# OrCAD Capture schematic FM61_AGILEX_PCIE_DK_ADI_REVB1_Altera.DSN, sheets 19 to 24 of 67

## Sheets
19 FPGA BANK 2C: size B
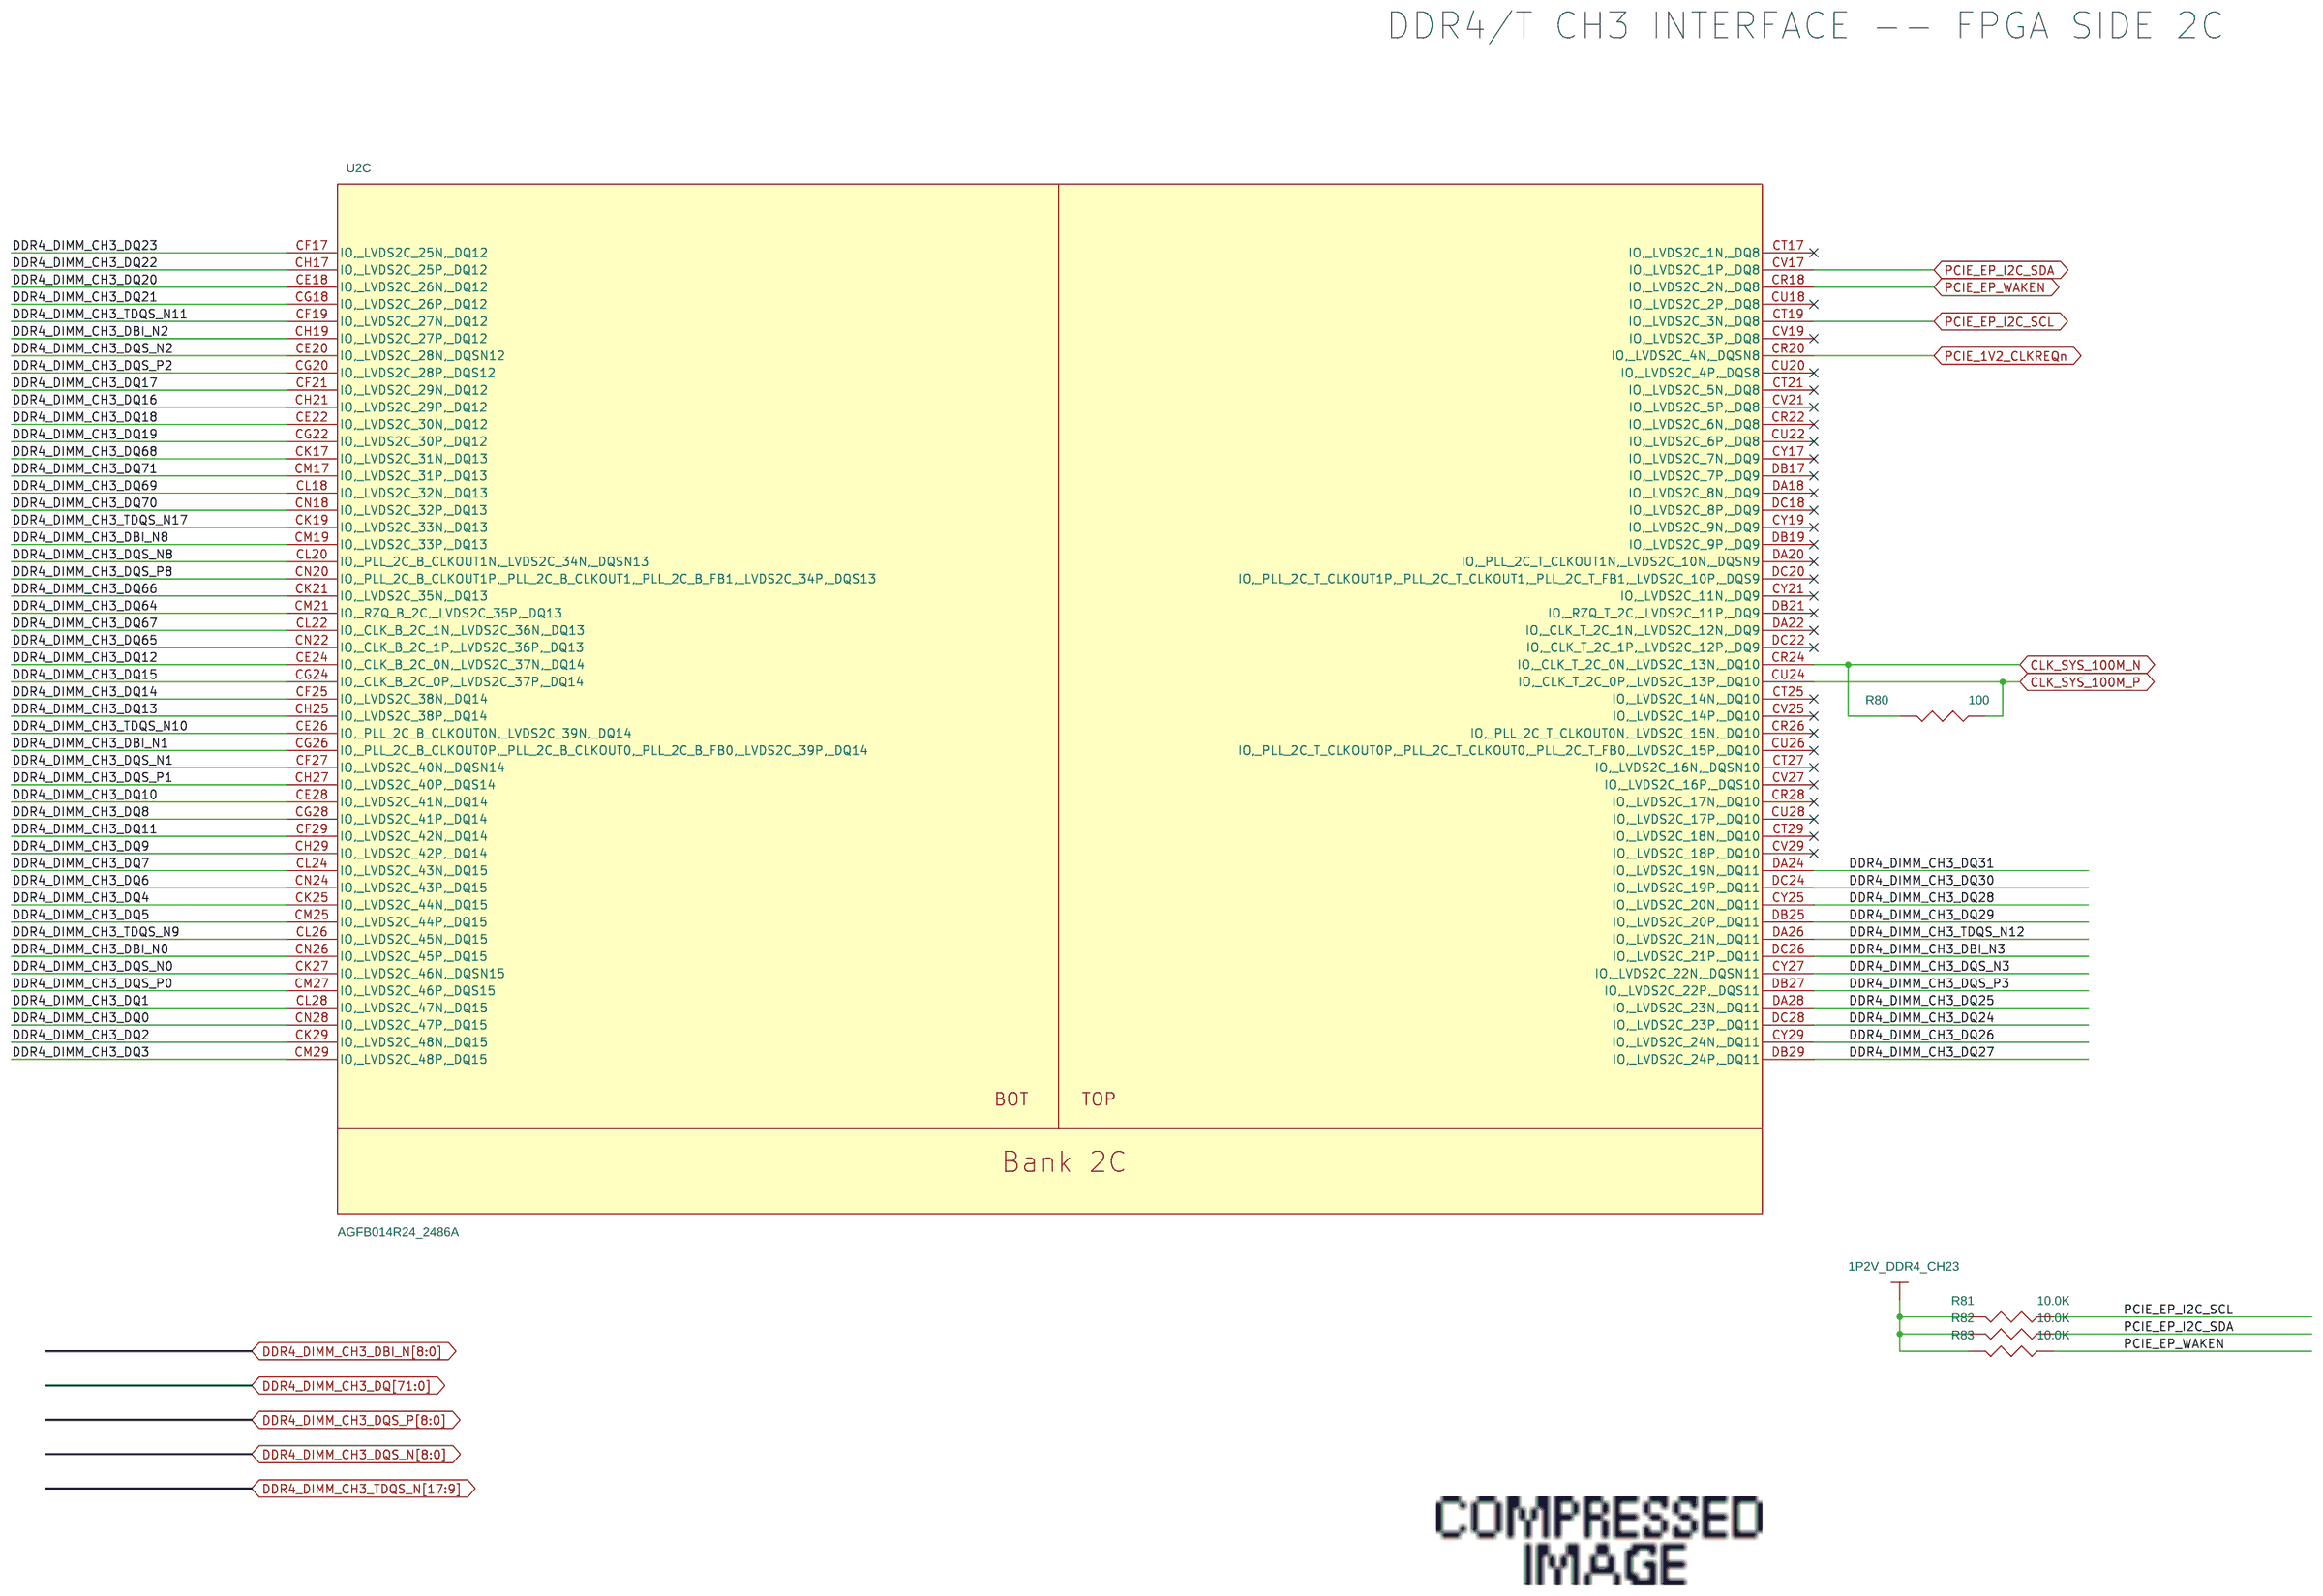
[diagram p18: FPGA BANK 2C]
20 FPGA BANK 2D: size B
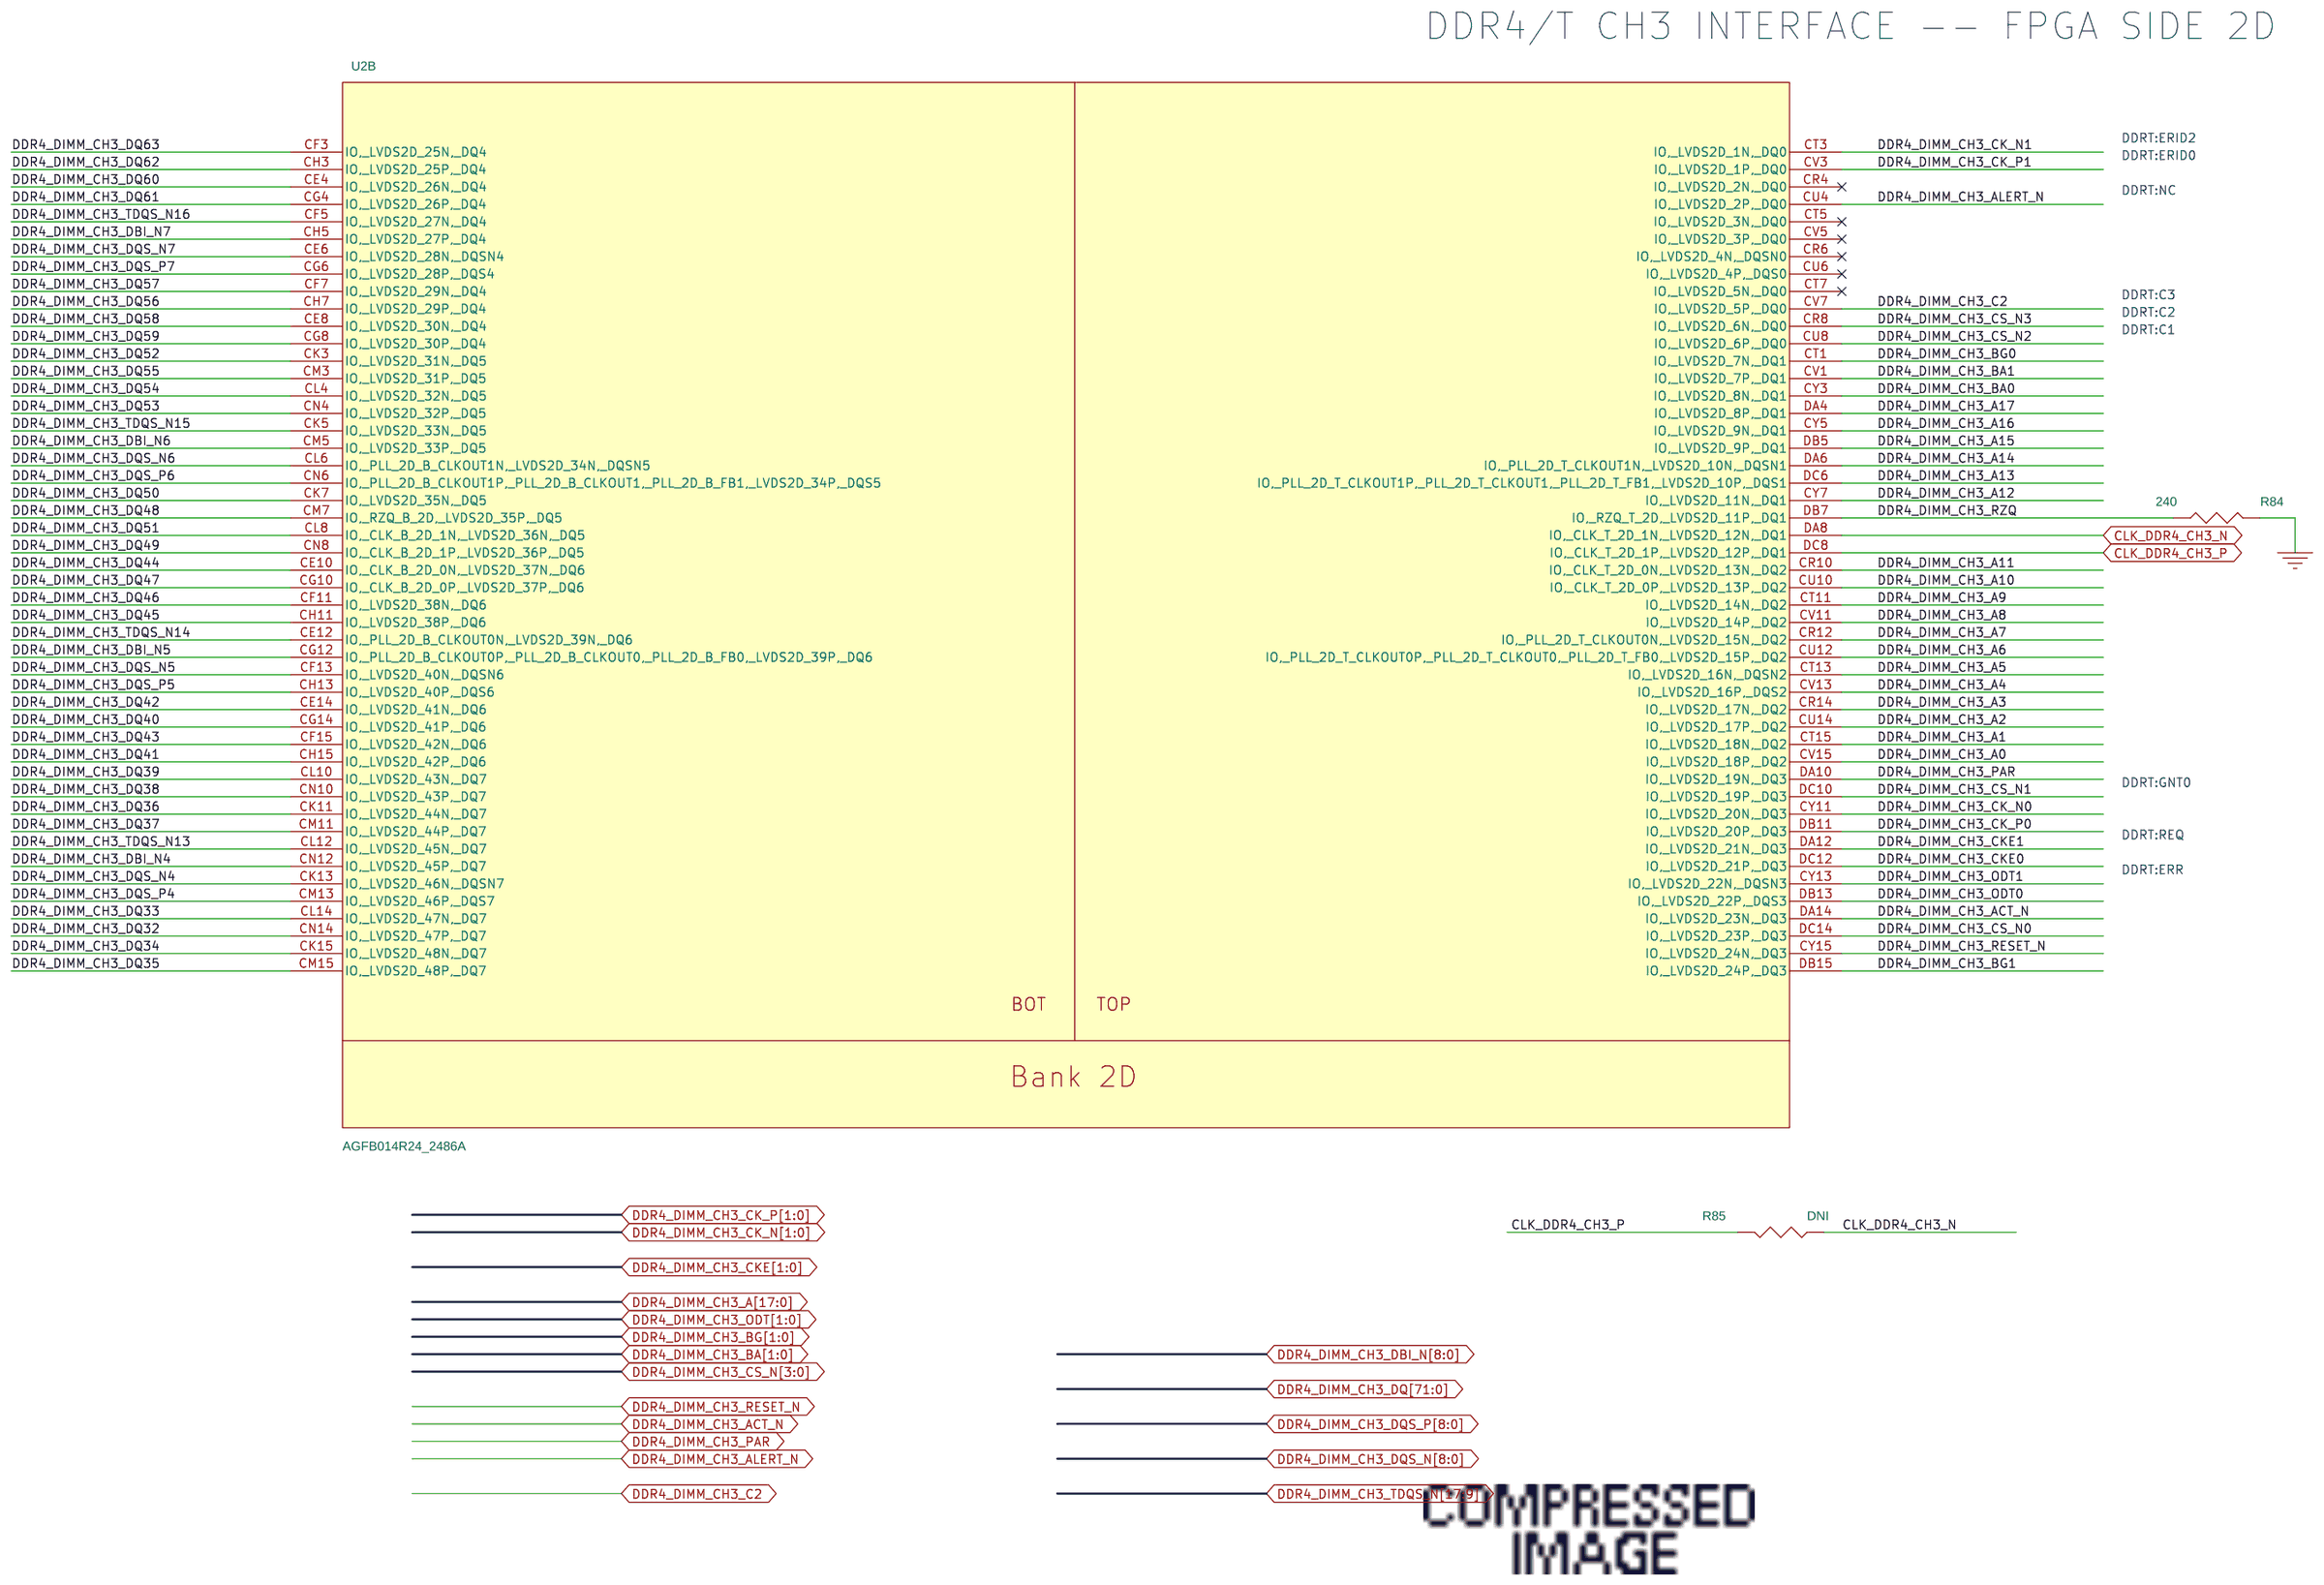
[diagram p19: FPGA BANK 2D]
21 FPGA BANK 9A: size B
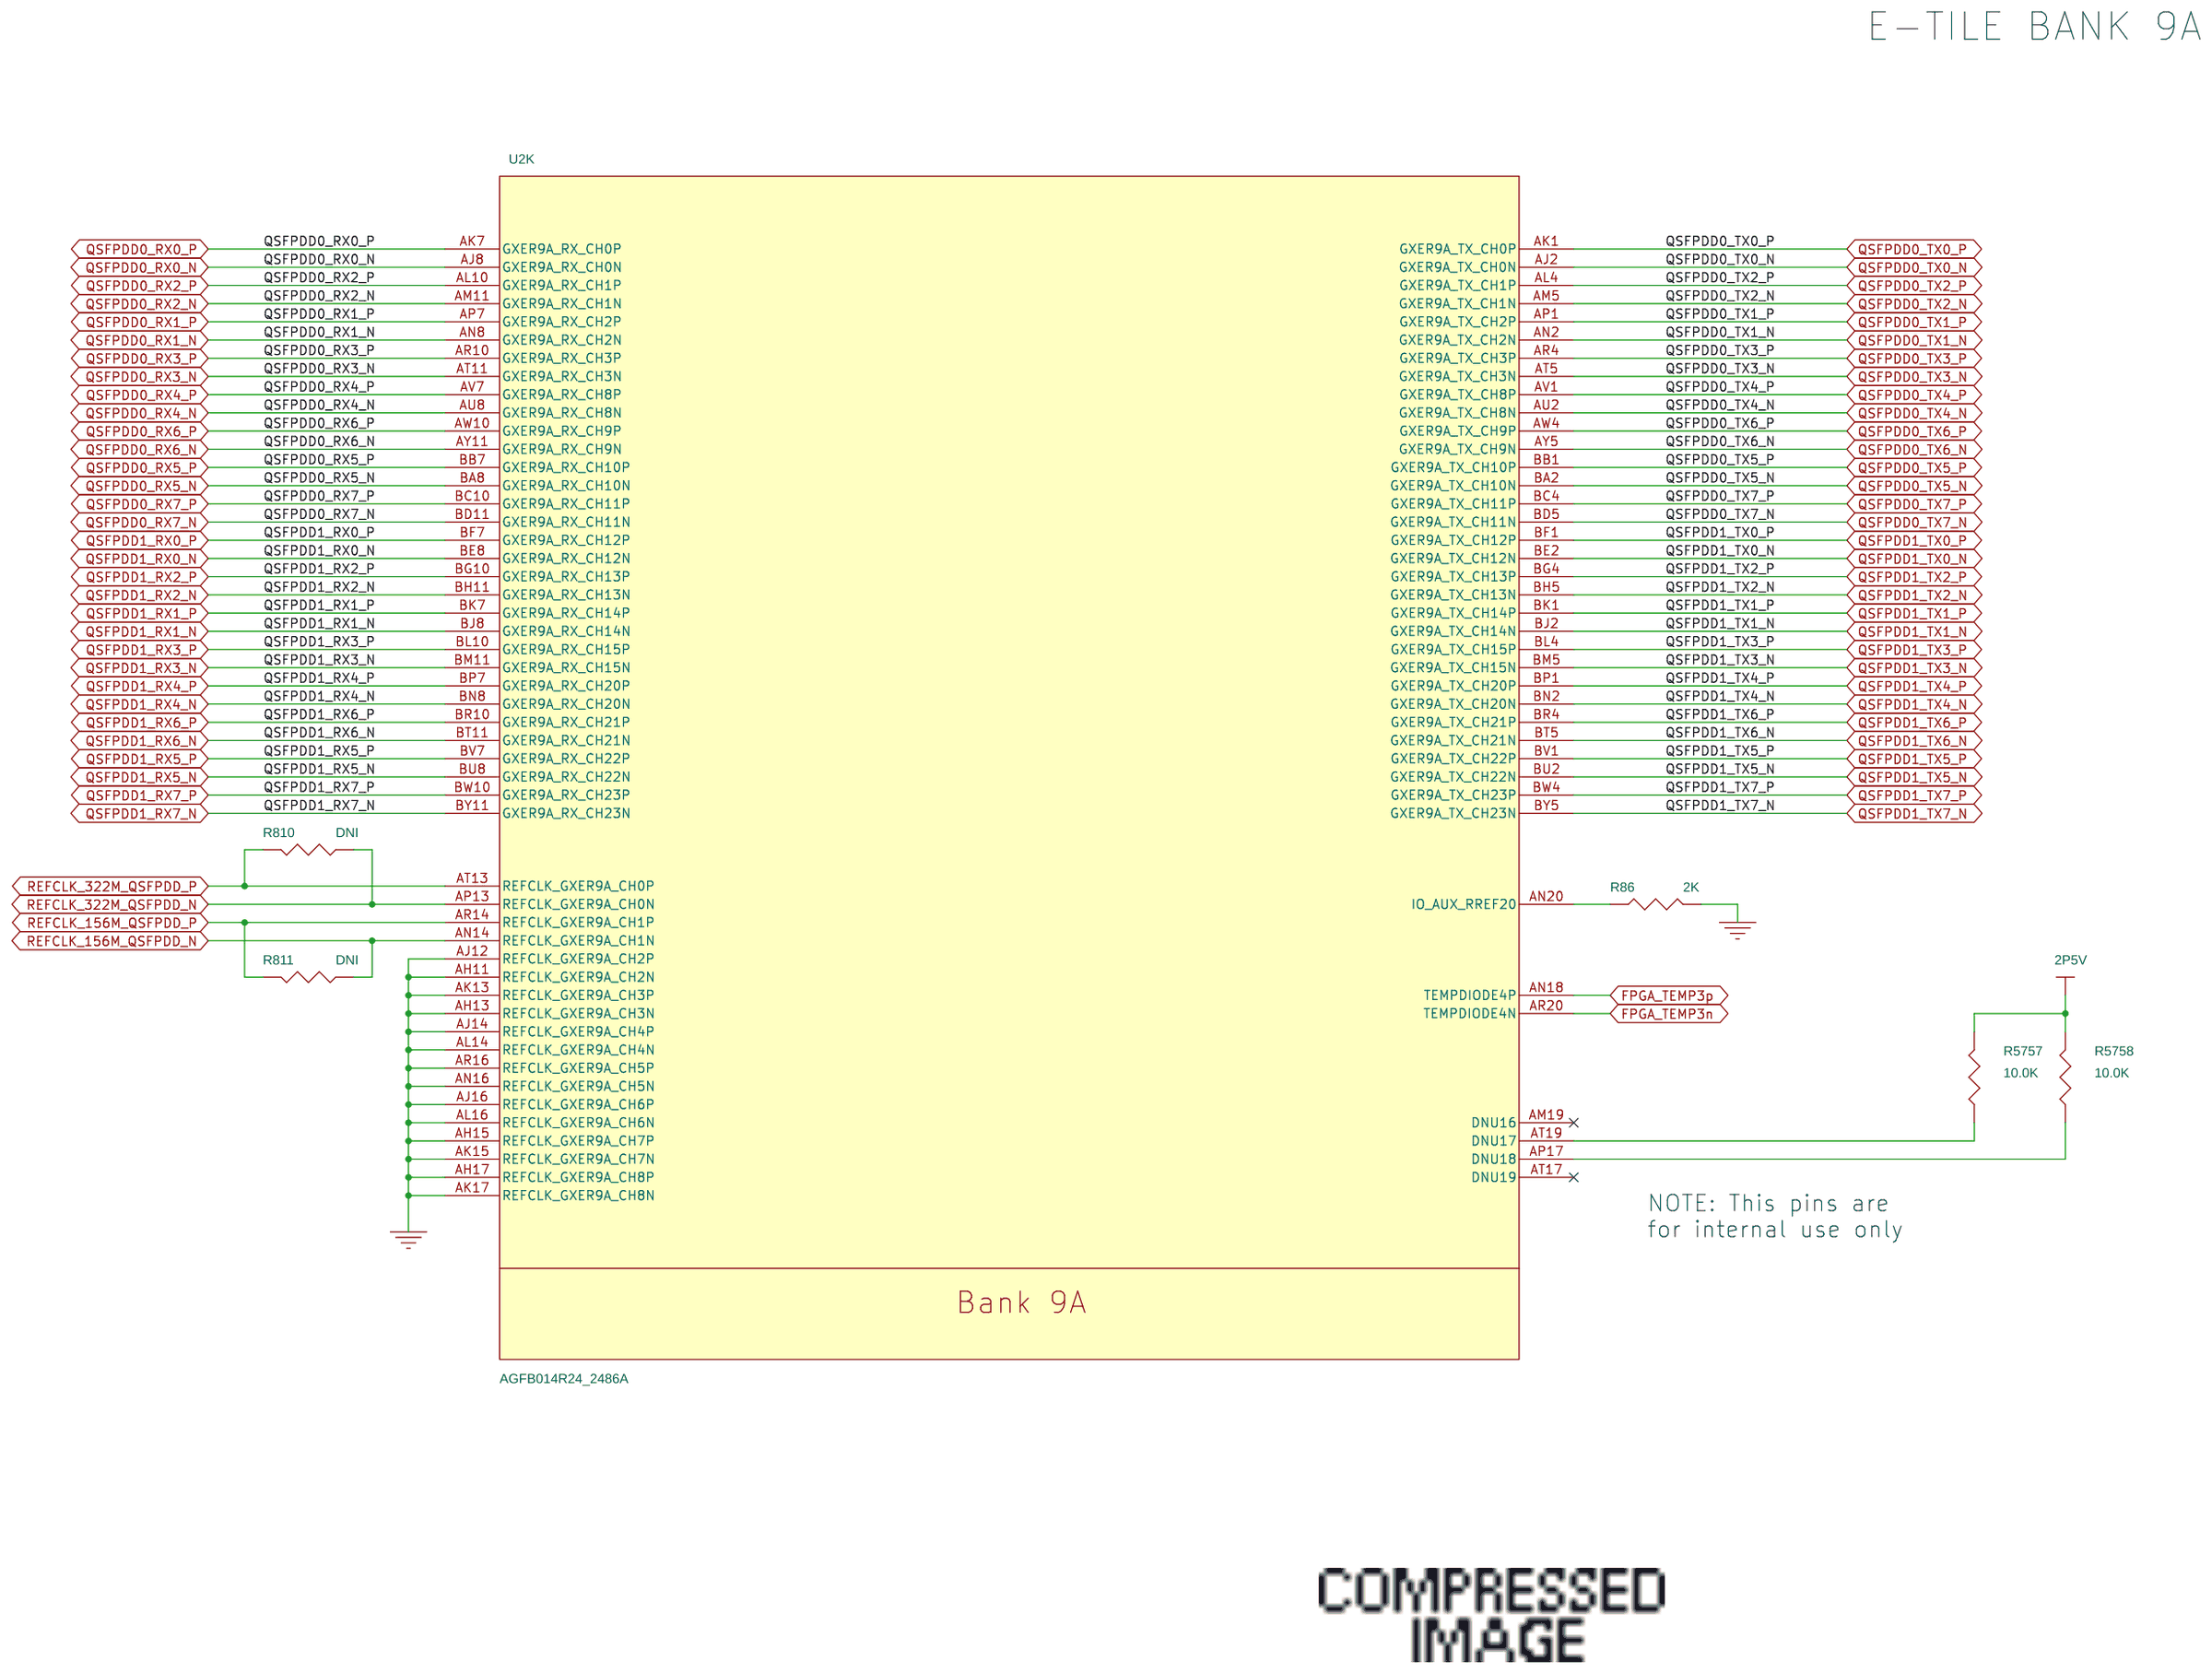
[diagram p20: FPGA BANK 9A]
22 FPGA BANK 10A: size B
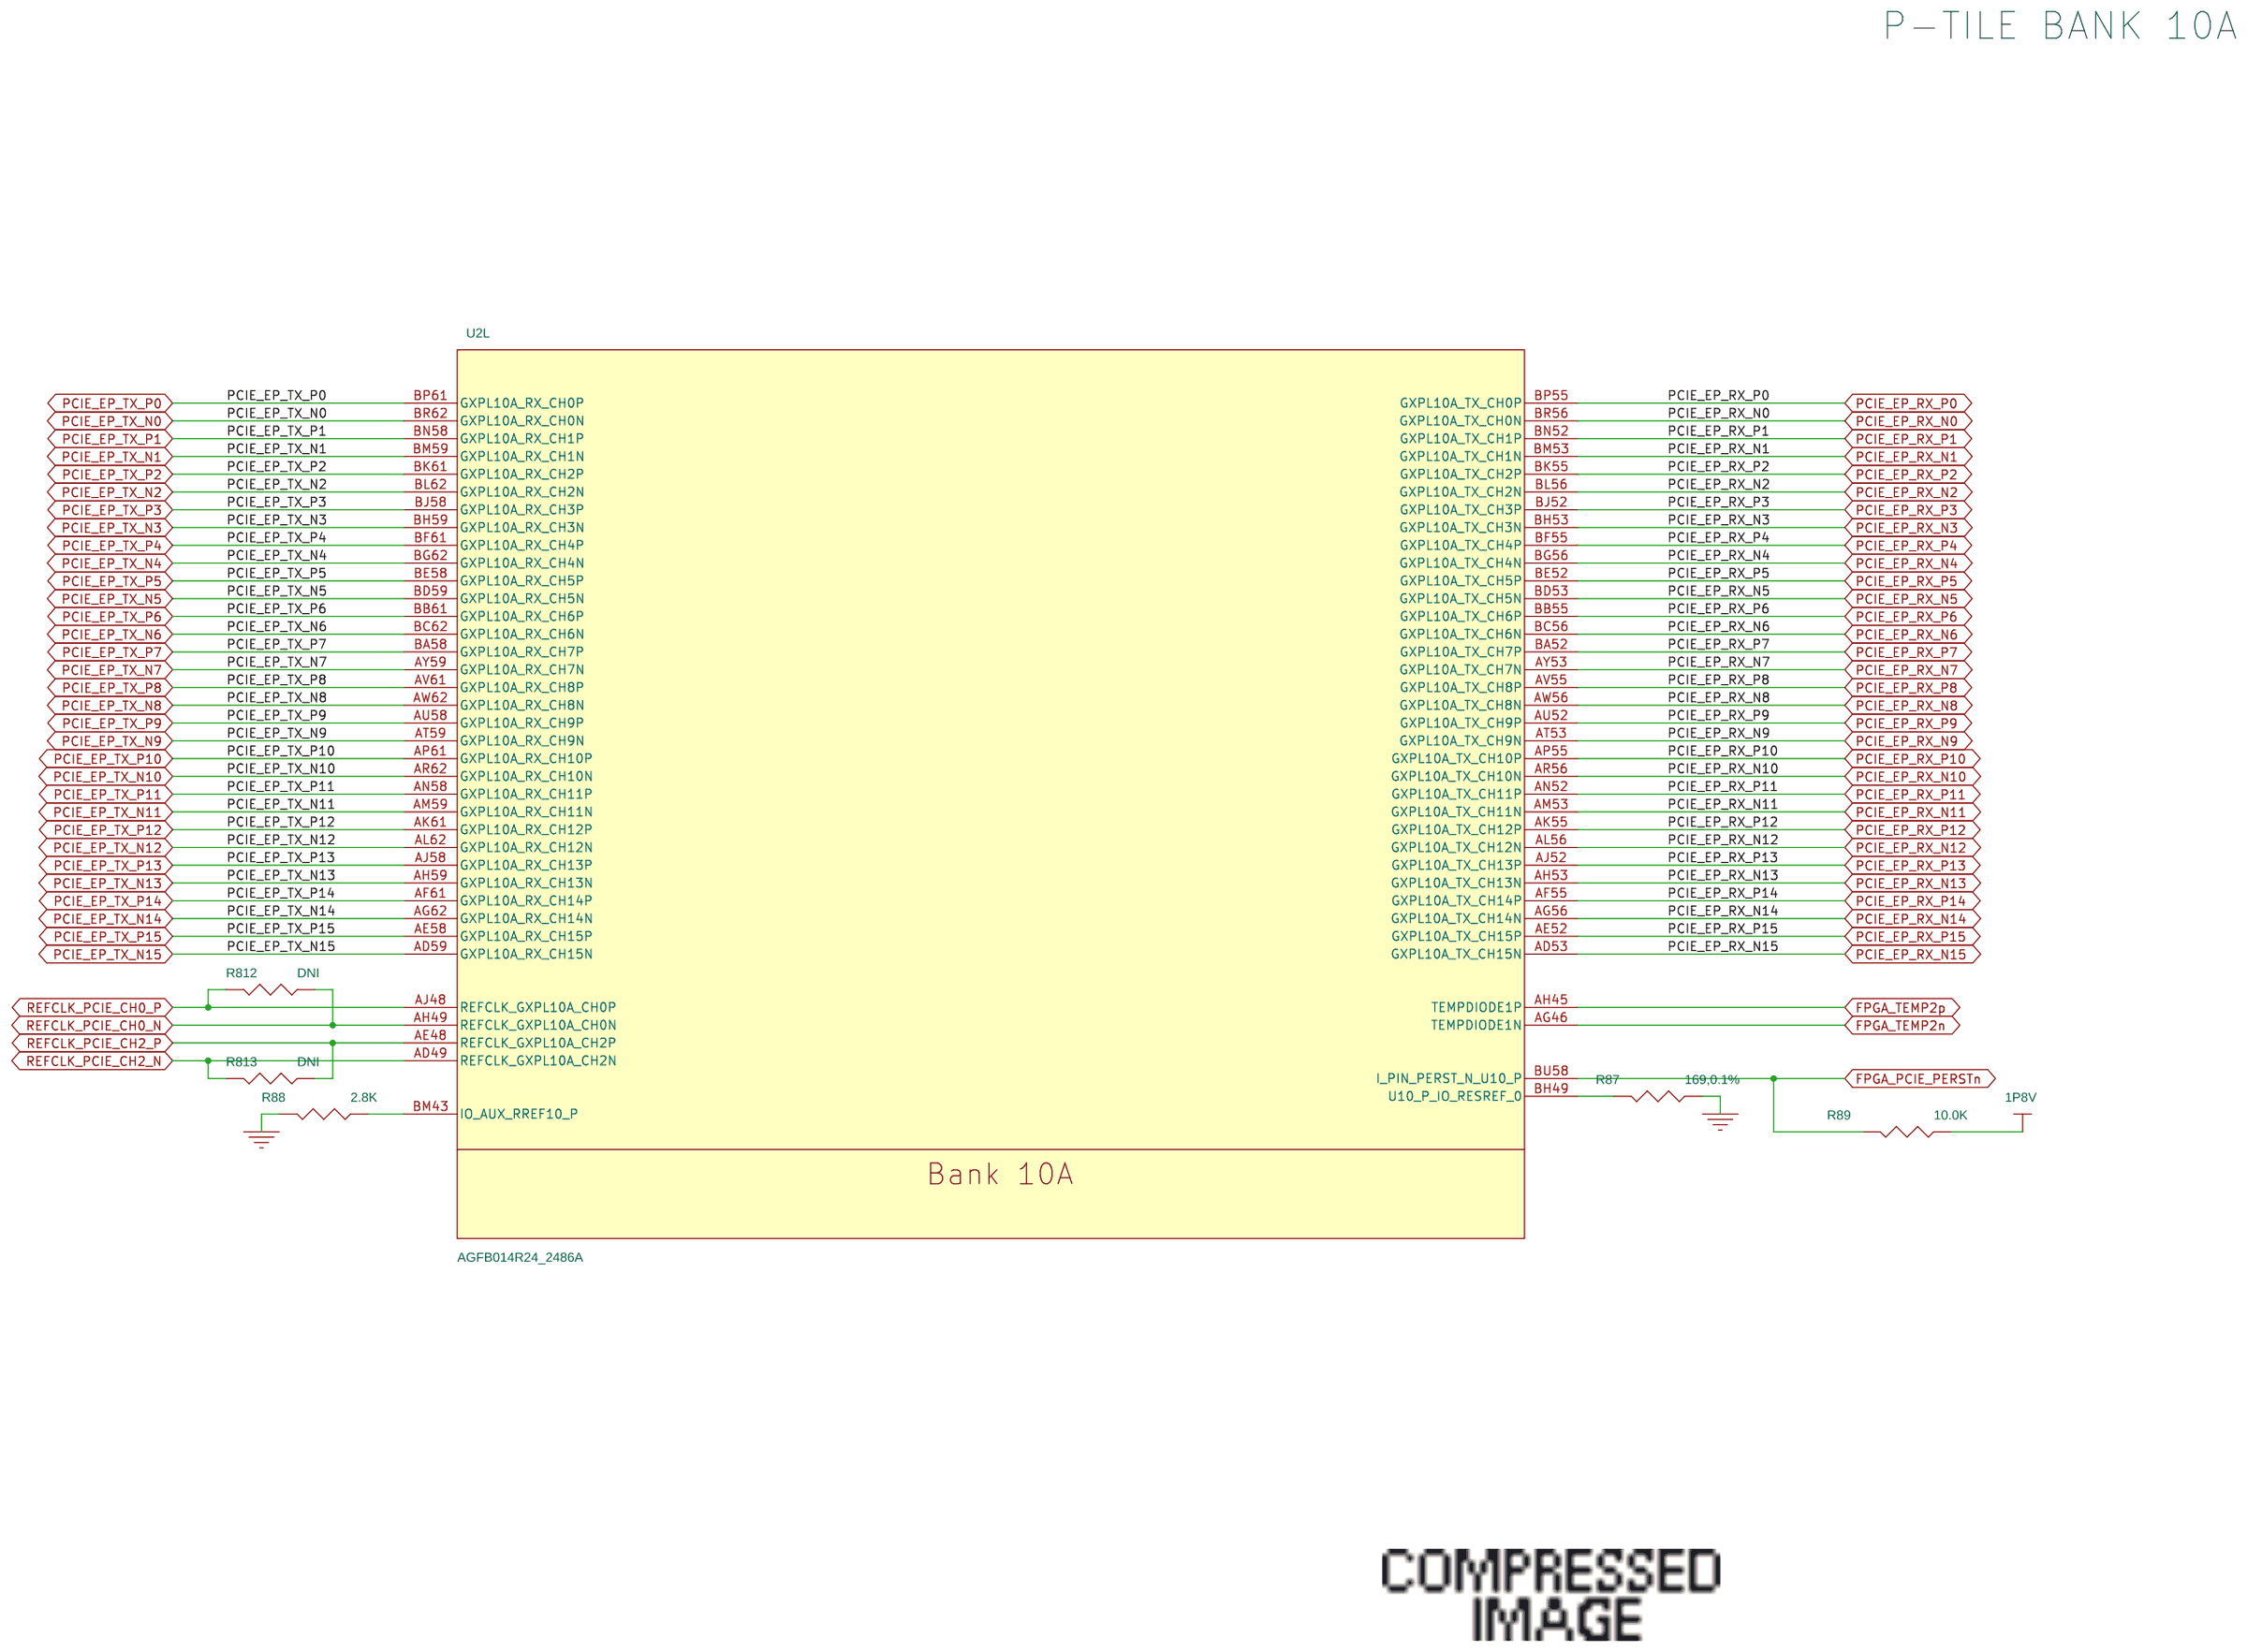
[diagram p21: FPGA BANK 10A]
23 QSFPDD0: size B
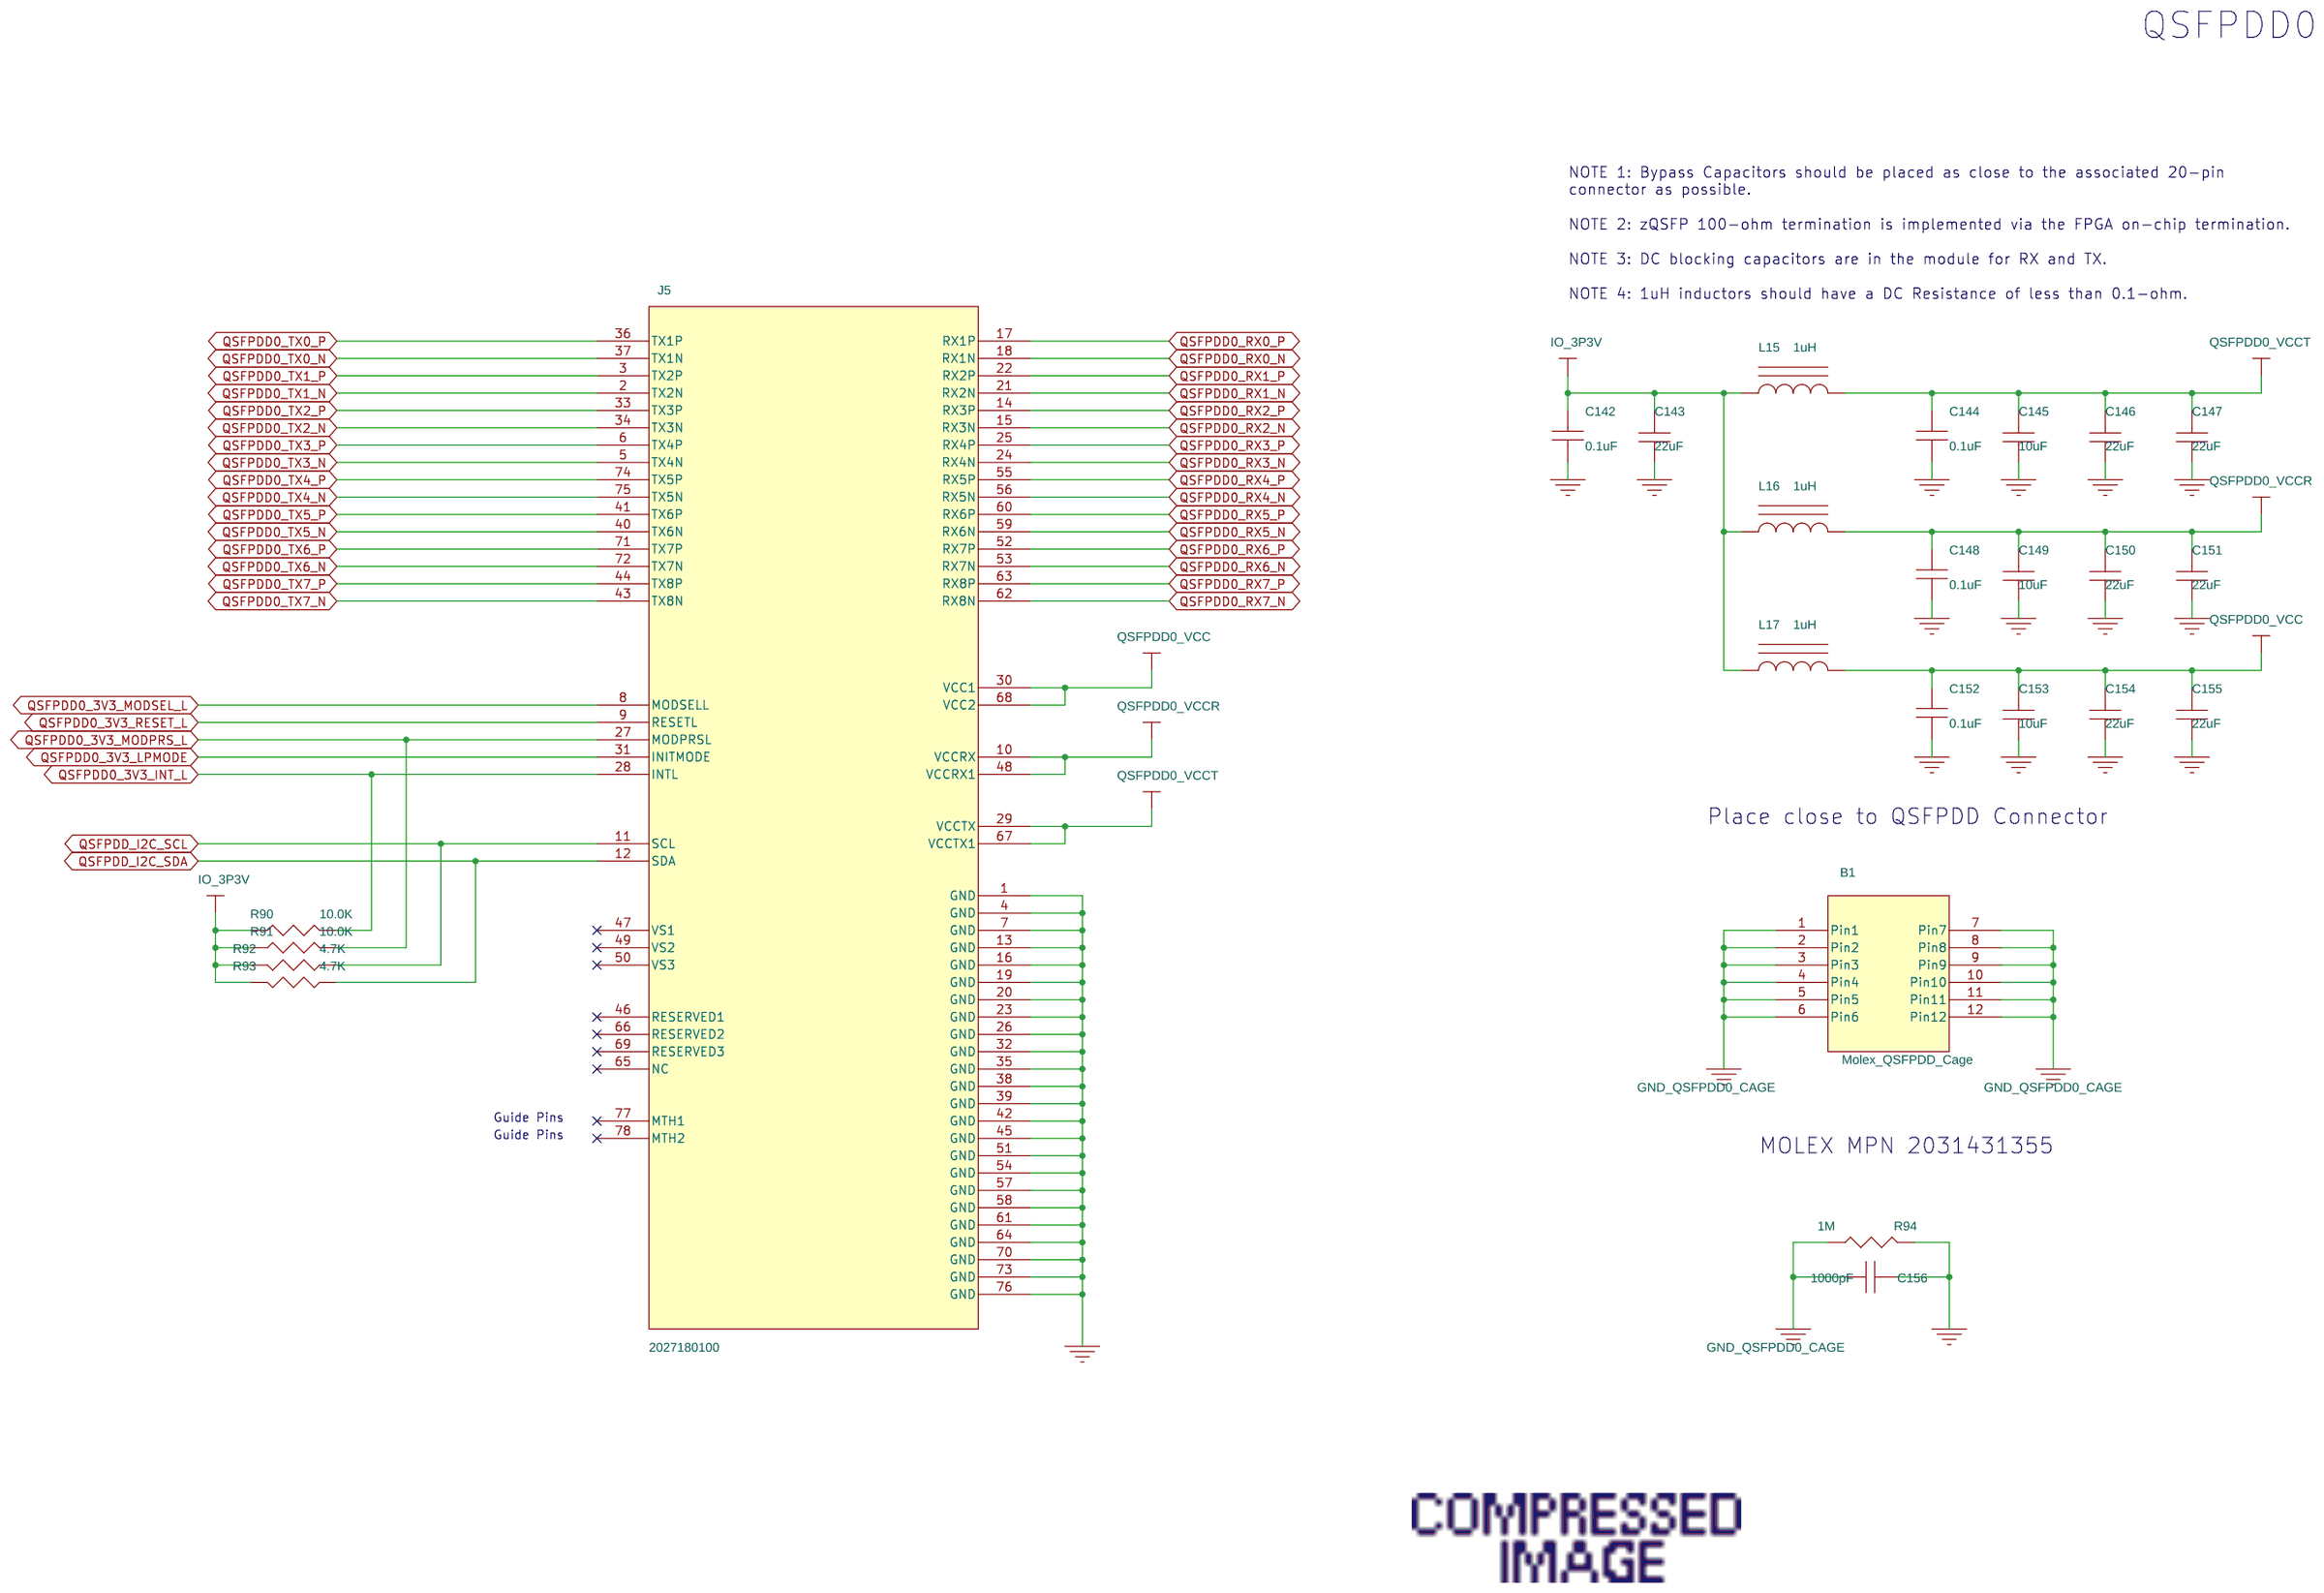
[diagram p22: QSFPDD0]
24 QSFPDD1: size B
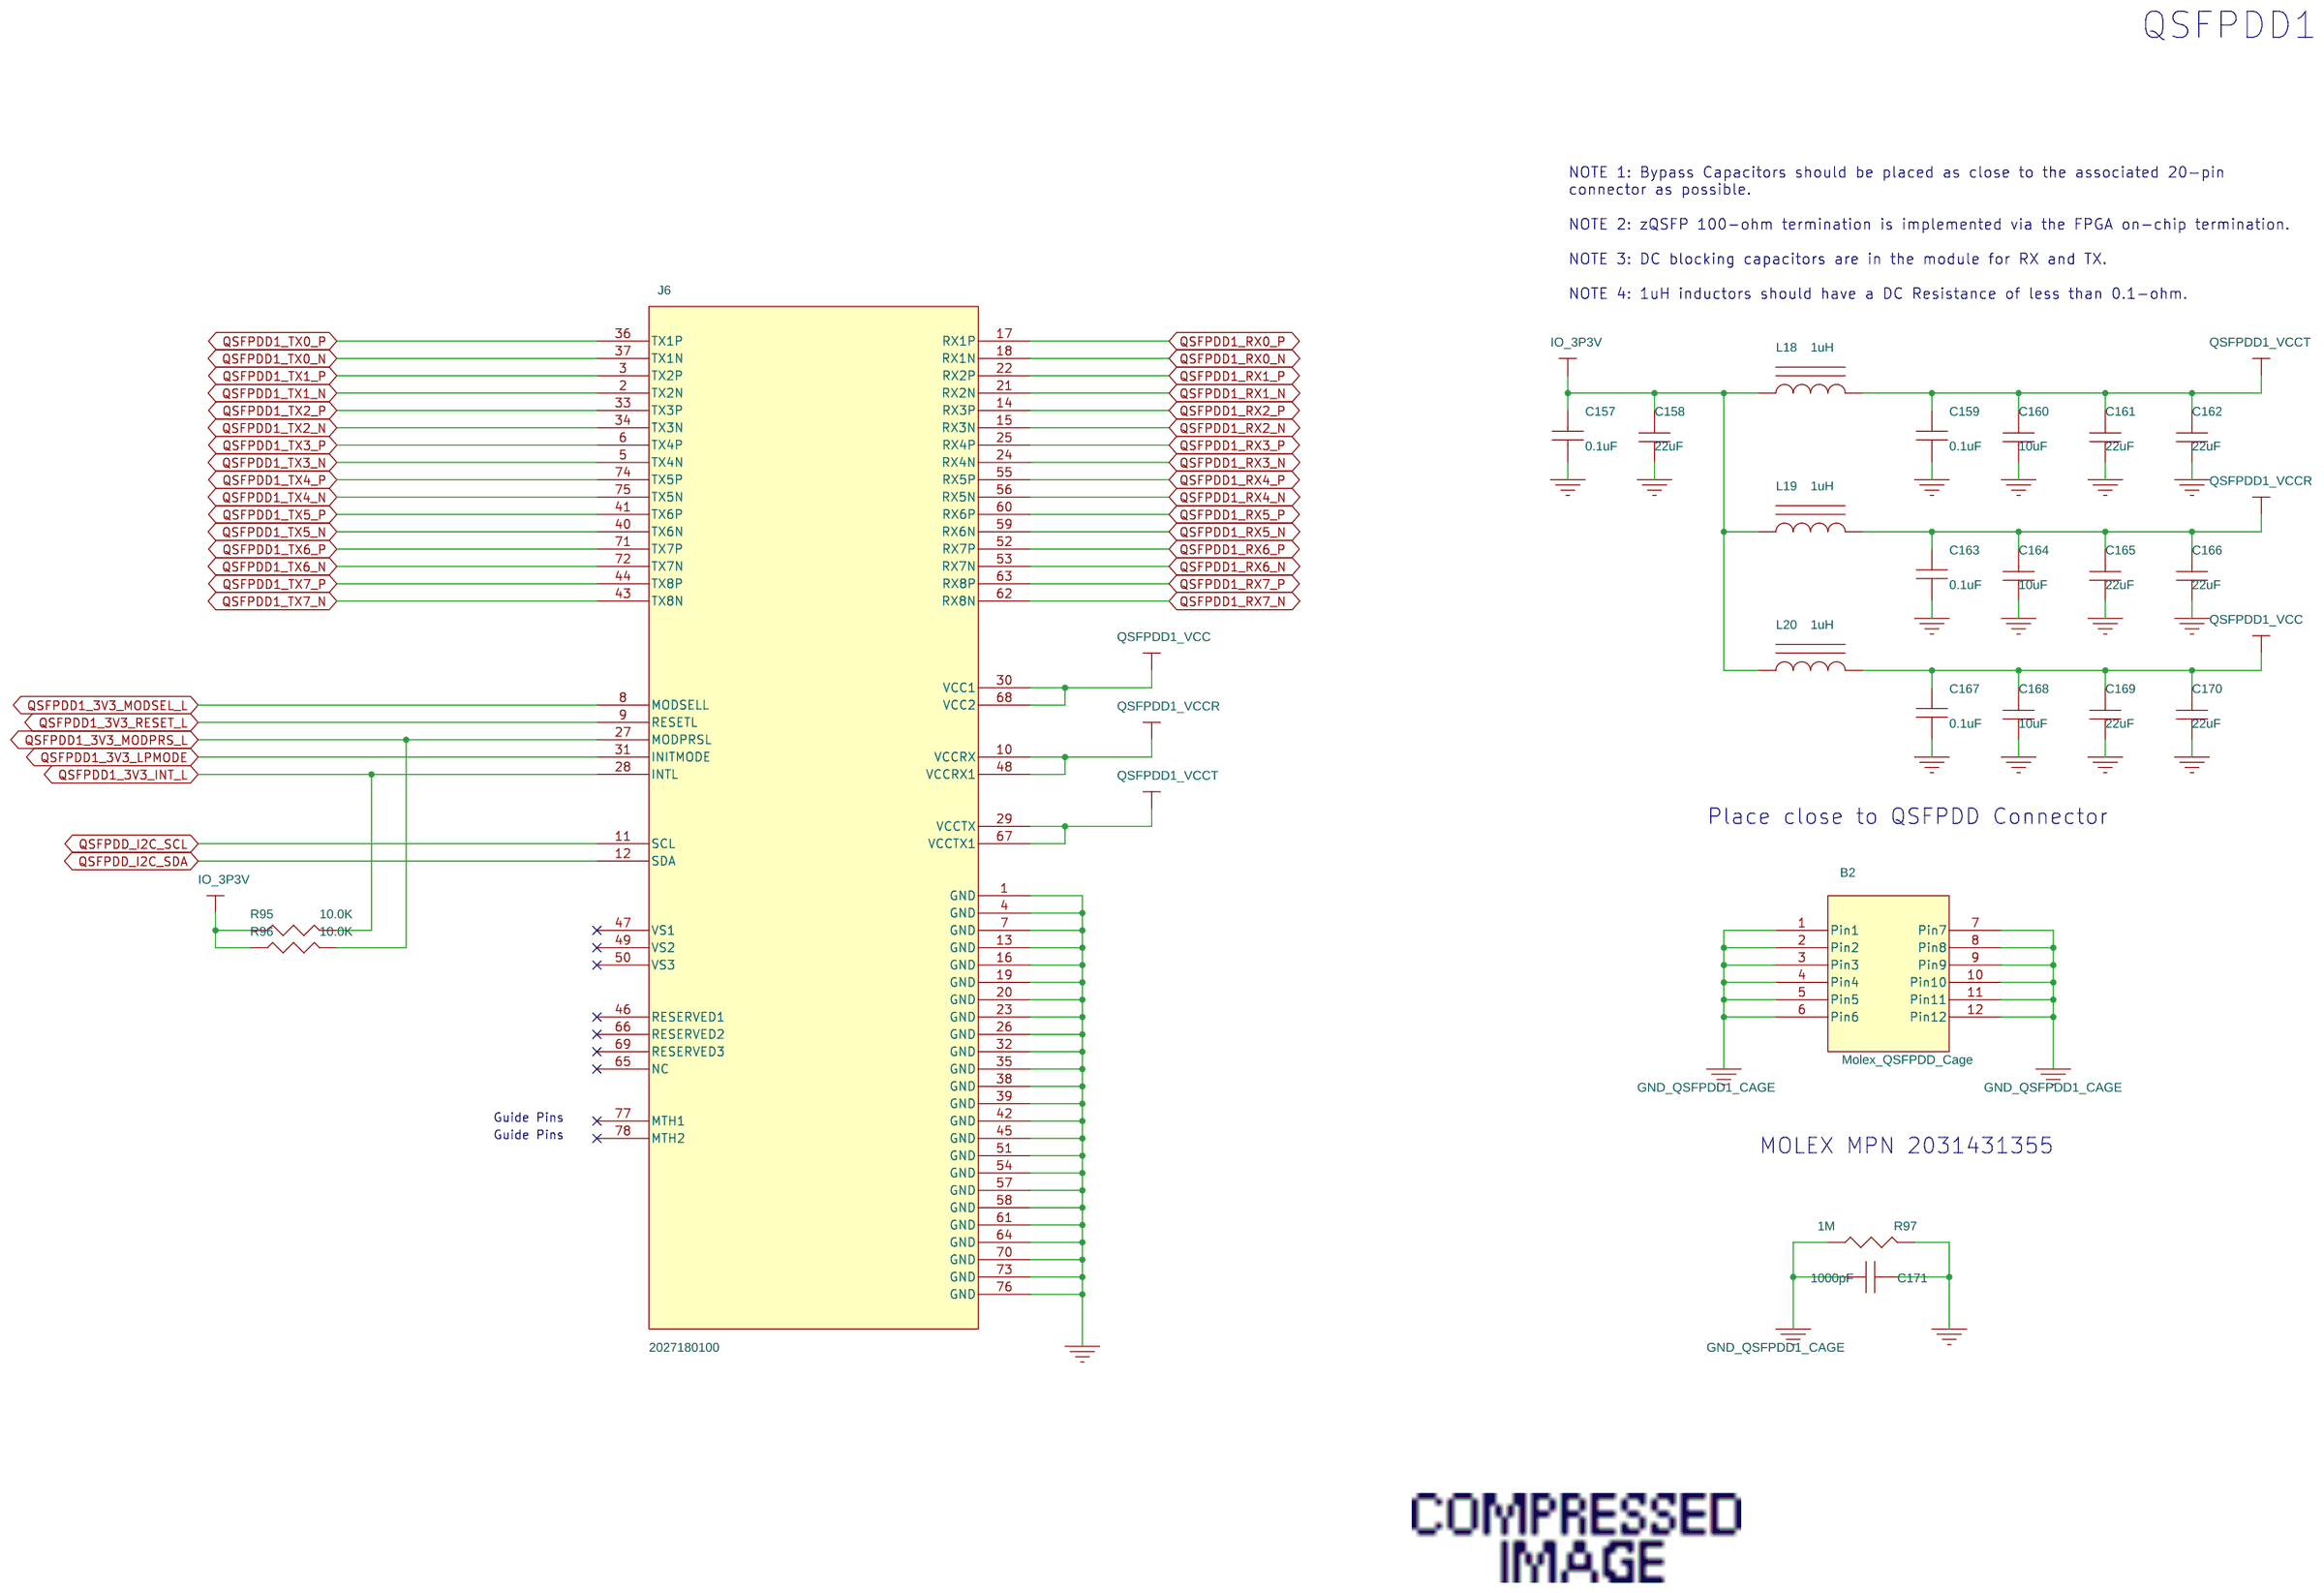
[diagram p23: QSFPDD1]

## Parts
sheet FPGA BANK 2C
R80  100  [0402]
R81  10.0K  [0402]
R82  10.0K  [0402]
R83  10.0K  [0402]
sheet FPGA BANK 2D
R84  240  [0402]
R85  DNI  [0402]
sheet FPGA BANK 9A
R86  2K  [0402]
R810  DNI  [0402]
R811  DNI  [0402]
R5757  10.0K  [0402]
R5758  10.0K  [0402]
sheet FPGA BANK 10A
R87  169,0.1%  [0402]
R88  2.8K  [0402]
R89  10.0K  [0402]
R812  DNI  [0402]
R813  DNI  [0402]
sheet FPGA Gnd 2
U2  AGFB014R24_2486A  [FBGA2486A_HEX]  (sections A,B,C,D,E,F,G,H,I,J,K,L,M,N,O,P,Q,R,S,T,U,V,W,X)
sheet QSFPDD0
B1  Molex_QSFPDD_Cage  [Molex_QSFPDD_Cage]
C142  0.1uF  [0402]
C143  22uF  [0603]
C144  0.1uF  [0402]
C145  10uF  [0603]
C146  22uF  [0603]
C147  22uF  [0603]
C148  0.1uF  [0402]
C149  10uF  [0603]
C150  22uF  [0603]
C151  22uF  [0603]
C152  0.1uF  [0402]
C153  10uF  [0603]
C154  22uF  [0603]
C155  22uF  [0603]
C156  1000pF  [1206]
J5  2027180100  [2027180100]
L15  1uH  [IFSC1008ABER1R0M01]
L16  1uH  [IFSC1008ABER1R0M01]
L17  1uH  [IFSC1008ABER1R0M01]
R90  10.0K  [0402]
R91  10.0K  [0402]
R92  4.7K  [0402]
R93  4.7K  [0402]
R94  1M  [0402]
sheet QSFPDD1
B2  Molex_QSFPDD_Cage  [Molex_QSFPDD_Cage]
C157  0.1uF  [0402]
C158  22uF  [0603]
C159  0.1uF  [0402]
C160  10uF  [0603]
C161  22uF  [0603]
C162  22uF  [0603]
C163  0.1uF  [0402]
C164  10uF  [0603]
C165  22uF  [0603]
C166  22uF  [0603]
C167  0.1uF  [0402]
C168  10uF  [0603]
C169  22uF  [0603]
C170  22uF  [0603]
C171  1000pF  [1206]
J6  2027180100  [2027180100]
L18  1uH  [IFSC1008ABER1R0M01]
L19  1uH  [IFSC1008ABER1R0M01]
L20  1uH  [IFSC1008ABER1R0M01]
R95  10.0K  [0402]
R96  10.0K  [0402]
R97  1M  [0402]

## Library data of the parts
R80 R85 R810-R813 = RESISTOR: RES,100 OHMS,1.0%,1/16W,0402; IPN: A36092-043; Item Num: P02-11381R; Lead Free Status: No; Manufacturer: Panasonic; Manufacturer Part Num: ERJ-2RKF1000X; Manufacturer's Part No.: ERJ-2RKF1000X; Num Pins: 2; Part Class: RESISTORS; Price: 0; RoHS Compliant: Yes
R81-R83 R89-R91 R95 R96 R5757 R5758 = RESISTOR: RES,10.0K OHMS,1.0%,1/16W, 0402; AGILE_LINK: http://sj-agile9app/Agile/PLMServlet?action=OpenEmailObject&classid=10000&objid=146548997; IPN: A93548-034; Item Num: P02-11364R; LIFECYCLE_PHASE: Active; Lead Free Status: No; MFR_LIFECYCLE: Active; Manufacturer: Panasonic; Manufacturer Part Num: ERJ-2RKF1002X; Num Pins: 2; PART_SUBCLASS: RESISTORS; POWER: 1/16W; RoHS Compliant: Yes; TOLERANCE: +/-1%
R84 = RESISTOR: RES - 240 OHM, 1/16W, 1%, 0402 SMD; IPN: K15783-001; Item Num: P02-15995R; LIFECYCLE_PHASE: Active; Lead Free Status: Lead Free; MFR_LIFECYCLE: Active; Manufacturer: Panasonic; Manufacturer Part Num: ERJ-2RKF2400X; Num Pins: 2; PART_SUBCLASS: RESISTORS; RoHS Compliant: RoHS Compliant
R86 = RESISTOR: RES 2K OHM 1/16W 1% 0402 SMD; IPN: J43524-001; Item Num: P02-17656R; Lead Free Status: Yes; Manufacturer: Panasonic; Manufacturer Part Num: ERJ-2RKF2001X; Num Pins: 2; Part Class: RESISTORS; Price: 0; RoHS Compliant: Yes
R87 = RESISTOR: RES SMD 169 OHM 0.1% 1/16W 0402; IPN: A93548-162; Lead Free Status: Yes; Manufacturer: Yageo; Manufacturer Part Num: RT0402BRD07169RL; Num Pins: 2; Part Class: Resistors; Price: 0
R88 = RESISTOR: RES SMD 2.8K OHM 1% 1/20W 0402; IPN: A93548-170; Lead Free Status: Yes; Manufacturer: yageo; Manufacturer Part Num: RT0402BRD072K8L; Num Pins: 2; Part Class: Resistors; Price: 0
U2 = FM6_2486A_V1.5: IPN: 99AH52
B1 B2 = Molex_QSFPDD_Cage: CONN_SFFP,QSDD,CGHS,10,RA,6PF,1,N/A; IPN: K23336-001; IPN No: K23336-001; Manufacturer: Molex; Manufacturer Part Num: 203143-1349
C142 C144 C148 C152 C157 C159 C163 C167 = CAP: CAPC,Y5V,0402,0.1UF,25V,+80/-20%; Dielectric: Y5V; IPN: K13560-001; Item Num: P03-15057R; LIFECYCLE_PHASE: Active; Lead Free Status: Lead Free; MFR_LIFECYCLE: Active; Manufacturer: Murata; Manufacturer Part Num: GRM155F51E104ZA01D; Num Pins: 2; PART_SUBCLASS: CAPACITORS; Part Class: CAPACITORS; RATED_VOLTAGE: 25V; RoHS Compliant: RoHS Compliant; Tolerance: +80%/-20%
C143 C146 C147 C150 C151 C154 C155 C158 C161 C162 C165 C166 C169 C170 = CAP: CAP CER 22UF 6.3V X6S 0603; AGILE_LINK: http://sj-agile9app/Agile/PLMServlet?action=OpenEmailObject&classid=10000&objid=257560276; IPN: H63299-001; Item Num: P03-17963R; LIFECYCLE_PHASE: Active; Lead Free Status: Not Lead Free; MFR_LIFECYCLE: Active; Manufacturer: Murata; Manufacturer Part Num: GRM188C80J226ME15D; Num Pins: 2; PART_SUBCLASS: CAPACITORS; RATED_VOLTAGE: 6.3V; RoHS Compliant: RoHS Compliant; TOLERANCE: 20%; Temperature Coefficient: X6S
C145 C149 C153 C160 C164 C168 = CAP: CAP CER 10UF 6.3V X6S 0603; AGILE_LINK: http://sj-agile9app/Agile/PLMServlet?action=OpenEmailObject&classid=10000&objid=257560276; IPN: K19402-001; Item Num: P03-17964R; LIFECYCLE_PHASE: Active; Lead Free Status: Not Lead Free; MFR_LIFECYCLE: Active; Manufacturer: TDK; Manufacturer Part Num: C1608X6S0J106M080AC; Num Pins: 2; PART_SUBCLASS: CAPACITORS; RATED_VOLTAGE: 6.3V; RoHS Compliant: RoHS Compliant; TOLERANCE: 20%; Temperature Coefficient: X6S
C156 C171 = CAP: CAP CER 1000PF 1000V X7R 1206; AGILE_LINK: http://sj-agile9app/Agile/PLMServlet?action=OpenEmailObject&classid=10000&objid=215384813; IPN: K13749-001; Item Num: P03-17910R; LIFECYCLE_PHASE: Active; Lead Free Status: Lead Free; MFR_LIFECYCLE: Active; Manufacturer: Murata; Manufacturer Part Num: GRM31BR73A102KW01L; Num Pins: 2; PACKAGING: Tape & Reel (TR); PART_SUBCLASS: CAPACITORS; RATED_VOLTAGE: 1000V; RoHS Compliant: RoHS Compliant; Supplier Part Num: GRM31BR73A102KW01L; Tolerance: +/-10%
J5 J6 = 2027180100: IPN: K21523-001
L15-L20 = INDUCTOR_IRON: IND, 1uH; IPN: D23343-007; Item Num: D23343-007; Manufacturer: Vishay Dale
R92 R93 = RESISTOR: RES 4.7K OHM 1/16W 5% 0402 SMD; IPN: H30885-001; Item Num: P02-14032R; Lead Free Status: No; Manufacturer: Panasonic; Manufacturer Part Num: ERJ-2GEJ472X; Manufacturer's Part No.: ERJ-2GEJ472X; Num Pins: 2; Part Class: RESISTORS; Price: 0; RoHS Compliant: Yes
R94 R97 = RESISTOR: RES,1M OHMS,5.0%,1/16W,0402; AGILE_LINK: http://sj-agile9app/Agile/PLMServlet?action=OpenEmailObject&classid=10000&objid=146548997; IPN: K15866-001; Item Num: P02-11390R; LIFECYCLE_PHASE: Active; Lead Free Status: No; MFR_LIFECYCLE: Active; Manufacturer: Panasonic; Manufacturer Part Num: ERJ-2GEJ105X; Num Pins: 2; PART_SUBCLASS: RESISTORS; POWER: 1/16W; RoHS Compliant: Yes; TOLERANCE: +/-5%

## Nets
GND: C142.2 C143.1 C144.2 C145.1 C146.1 C147.1 C148.2 C149.1 C150.1 C151.1 C152.2 C153.1 C154.1 C155.1 C156.2 C157.2 C158.1 C159.2 C160.1 C161.1 C162.1 C163.2 C164.1 C165.1 C166.1 C167.2 C168.1 C169.1 C170.1 C171.2 J5.1(GND) J5.4(GND) J5.7(GND) J5.13(GND) J5.16(GND) J5.19(GND) J5.20(GND) J5.23(GND) J5.26(GND) J5.32(GND) J5.35(GND) J5.38(GND) J5.39(GND) J5.42(GND) J5.45(GND) J5.51(GND) J5.54(GND) J5.57(GND) J5.58(GND) J5.61(GND) J5.64(GND) J5.70(GND) J5.73(GND) J5.76(GND) J6.1(GND) J6.4(GND) J6.7(GND) J6.13(GND) J6.16(GND) J6.19(GND) J6.20(GND) J6.23(GND) J6.26(GND) J6.32(GND) J6.35(GND) J6.38(GND) J6.39(GND) J6.42(GND) J6.45(GND) J6.51(GND) J6.54(GND) J6.57(GND) J6.58(GND) J6.61(GND) J6.64(GND) J6.70(GND) J6.73(GND) J6.76(GND) R84.2 R86.2 R87.1 R88.1 R94.1 R97.1 U2.AH11(REFCLK_GXER9A_CH2N) U2.AH13(REFCLK_GXER9A_CH3N) U2.AH15(REFCLK_GXER9A_CH7P) U2.AH17(REFCLK_GXER9A_CH8P) U2.AJ12(REFCLK_GXER9A_CH2P) U2.AJ14(REFCLK_GXER9A_CH4P) U2.AJ16(REFCLK_GXER9A_CH6P) U2.AK13(REFCLK_GXER9A_CH3P) U2.AK15(REFCLK_GXER9A_CH7N) U2.AK17(REFCLK_GXER9A_CH8N) U2.AL14(REFCLK_GXER9A_CH4N) U2.AL16(REFCLK_GXER9A_CH6N) U2.AN16(REFCLK_GXER9A_CH5N) U2.AR16(REFCLK_GXER9A_CH5P) ; also on sheet 9 11 12 13 14 15 17 18 25 26 28 29 30 31 32 34 35 36 37 38 39 40 41 42 43 44 45 46 47 48 49 50 51 52 53 54 55 56 57 58 59 60 61 62 63 64 65 66
GND_QSFPDD0_CAGE: B1.1(Pin1) B1.2(Pin2) B1.3(Pin3) B1.4(Pin4) B1.5(Pin5) B1.6(Pin6) B1.7(Pin7) B1.8(Pin8) B1.9(Pin9) B1.10(Pin10) B1.11(Pin11) B1.12(Pin12) C156.1 R94.2
GND_QSFPDD1_CAGE: B2.1(Pin1) B2.2(Pin2) B2.3(Pin3) B2.4(Pin4) B2.5(Pin5) B2.6(Pin6) B2.7(Pin7) B2.8(Pin8) B2.9(Pin9) B2.10(Pin10) B2.11(Pin11) B2.12(Pin12) C171.1 R97.2
1p2V_DDR4_CH23: R81.2 R82.2 R83.2 ; also on sheet 15 16 18 25 34 46 61 62 66
1p8V: R89.1 ; also on sheet 34 46 54 65
2p5V: R5757.2 R5758.2 ; also on sheet 9 12 15 18 34 38 63
CLK_DDR4_CH3_N: R85.1 U2.DA8(IO,_CLK_T_2D_1N,_LVDS2D_12N,_DQ1) ; also on sheet 38
CLK_DDR4_CH3_P: R85.2 U2.DC8(IO,_CLK_T_2D_1P,_LVDS2D_12P,_DQ1) ; also on sheet 38
CLK_SYS_100M_N: R80.2 U2.CR24(IO,_CLK_T_2C_0N,_LVDS2C_13N,_DQ10) ; also on sheet 38
CLK_SYS_100M_P: R80.1 U2.CU24(IO,_CLK_T_2C_0P,_LVDS2C_13P,_DQ10) ; also on sheet 38
DDR4_DIMM_CH3_A0: U2.CV15(IO,_LVDS2D_18P,_DQ2) ; also on sheet 18
DDR4_DIMM_CH3_A1: U2.CT15(IO,_LVDS2D_18N,_DQ2) ; also on sheet 18
DDR4_DIMM_CH3_A2: U2.CU14(IO,_LVDS2D_17P,_DQ2) ; also on sheet 18
DDR4_DIMM_CH3_A3: U2.CR14(IO,_LVDS2D_17N,_DQ2) ; also on sheet 18
DDR4_DIMM_CH3_A4: U2.CV13(IO,_LVDS2D_16P,_DQS2) ; also on sheet 18
DDR4_DIMM_CH3_A5: U2.CT13(IO,_LVDS2D_16N,_DQSN2) ; also on sheet 18
DDR4_DIMM_CH3_A6: U2.CU12(IO,_PLL_2D_T_CLKOUT0P,_PLL_2D_T_CLKOUT0,_PLL_2D_T_FB0,_LVDS2D_15P,_DQ2) ; also on sheet 18
DDR4_DIMM_CH3_A7: U2.CR12(IO,_PLL_2D_T_CLKOUT0N,_LVDS2D_15N,_DQ2) ; also on sheet 18
DDR4_DIMM_CH3_A8: U2.CV11(IO,_LVDS2D_14P,_DQ2) ; also on sheet 18
DDR4_DIMM_CH3_A9: U2.CT11(IO,_LVDS2D_14N,_DQ2) ; also on sheet 18
DDR4_DIMM_CH3_A10: U2.CU10(IO,_CLK_T_2D_0P,_LVDS2D_13P,_DQ2) ; also on sheet 18
DDR4_DIMM_CH3_A11: U2.CR10(IO,_CLK_T_2D_0N,_LVDS2D_13N,_DQ2) ; also on sheet 18
DDR4_DIMM_CH3_A12: U2.CY7(IO,_LVDS2D_11N,_DQ1) ; also on sheet 18
DDR4_DIMM_CH3_A13: U2.DC6(IO,_PLL_2D_T_CLKOUT1P,_PLL_2D_T_CLKOUT1,_PLL_2D_T_FB1,_LVDS2D_10P,_DQS1) ; also on sheet 18
DDR4_DIMM_CH3_A14: U2.DA6(IO,_PLL_2D_T_CLKOUT1N,_LVDS2D_10N,_DQSN1) ; also on sheet 18
DDR4_DIMM_CH3_A15: U2.DB5(IO,_LVDS2D_9P,_DQ1) ; also on sheet 18
DDR4_DIMM_CH3_A16: U2.CY5(IO,_LVDS2D_9N,_DQ1) ; also on sheet 18
DDR4_DIMM_CH3_A17: U2.DA4(IO,_LVDS2D_8P,_DQ1) ; also on sheet 18
DDR4_DIMM_CH3_ACT_N: U2.DA14(IO,_LVDS2D_23N,_DQ3) ; also on sheet 18
DDR4_DIMM_CH3_ALERT_N: U2.CU4(IO,_LVDS2D_2P,_DQ0) ; also on sheet 18
DDR4_DIMM_CH3_BA0: U2.CY3(IO,_LVDS2D_8N,_DQ1) ; also on sheet 18
DDR4_DIMM_CH3_BA1: U2.CV1(IO,_LVDS2D_7P,_DQ1) ; also on sheet 18
DDR4_DIMM_CH3_BG0: U2.CT1(IO,_LVDS2D_7N,_DQ1) ; also on sheet 18
DDR4_DIMM_CH3_BG1: U2.DB15(IO,_LVDS2D_24P,_DQ3) ; also on sheet 18
DDR4_DIMM_CH3_C2: U2.CV7(IO,_LVDS2D_5P,_DQ0) ; also on sheet 18
DDR4_DIMM_CH3_CK_N0: U2.CY11(IO,_LVDS2D_20N,_DQ3) ; also on sheet 18
DDR4_DIMM_CH3_CK_N1: U2.CT3(IO,_LVDS2D_1N,_DQ0) ; also on sheet 18
DDR4_DIMM_CH3_CK_P0: U2.DB11(IO,_LVDS2D_20P,_DQ3) ; also on sheet 18
DDR4_DIMM_CH3_CK_P1: U2.CV3(IO,_LVDS2D_1P,_DQ0) ; also on sheet 18
DDR4_DIMM_CH3_CKE0: U2.DC12(IO,_LVDS2D_21P,_DQ3) ; also on sheet 18
DDR4_DIMM_CH3_CKE1: U2.DA12(IO,_LVDS2D_21N,_DQ3) ; also on sheet 18
DDR4_DIMM_CH3_CS_N0: U2.DC14(IO,_LVDS2D_23P,_DQ3) ; also on sheet 18
DDR4_DIMM_CH3_CS_N1: U2.DC10(IO,_LVDS2D_19P,_DQ3) ; also on sheet 18
DDR4_DIMM_CH3_CS_N2: U2.CU8(IO,_LVDS2D_6P,_DQ0) ; also on sheet 18
DDR4_DIMM_CH3_CS_N3: U2.CR8(IO,_LVDS2D_6N,_DQ0) ; also on sheet 18
DDR4_DIMM_CH3_DBI_N0: U2.CN26(IO,_LVDS2C_45P,_DQ15) ; also on sheet 18
DDR4_DIMM_CH3_DBI_N1: U2.CG26(IO,_PLL_2C_B_CLKOUT0P,_PLL_2C_B_CLKOUT0,_PLL_2C_B_FB0,_LVDS2C_39P,_DQ14) ; also on sheet 18
DDR4_DIMM_CH3_DBI_N2: U2.CH19(IO,_LVDS2C_27P,_DQ12) ; also on sheet 18
DDR4_DIMM_CH3_DBI_N3: U2.DC26(IO,_LVDS2C_21P,_DQ11) ; also on sheet 18
DDR4_DIMM_CH3_DBI_N4: U2.CN12(IO,_LVDS2D_45P,_DQ7) ; also on sheet 18
DDR4_DIMM_CH3_DBI_N5: U2.CG12(IO,_PLL_2D_B_CLKOUT0P,_PLL_2D_B_CLKOUT0,_PLL_2D_B_FB0,_LVDS2D_39P,_DQ6) ; also on sheet 18
DDR4_DIMM_CH3_DBI_N6: U2.CM5(IO,_LVDS2D_33P,_DQ5) ; also on sheet 18
DDR4_DIMM_CH3_DBI_N7: U2.CH5(IO,_LVDS2D_27P,_DQ4) ; also on sheet 18
DDR4_DIMM_CH3_DBI_N8: U2.CM19(IO,_LVDS2C_33P,_DQ13) ; also on sheet 18
DDR4_DIMM_CH3_DQ0: U2.CN28(IO,_LVDS2C_47P,_DQ15) ; also on sheet 18
DDR4_DIMM_CH3_DQ1: U2.CL28(IO,_LVDS2C_47N,_DQ15) ; also on sheet 18
DDR4_DIMM_CH3_DQ2: U2.CK29(IO,_LVDS2C_48N,_DQ15) ; also on sheet 18
DDR4_DIMM_CH3_DQ3: U2.CM29(IO,_LVDS2C_48P,_DQ15) ; also on sheet 18
DDR4_DIMM_CH3_DQ4: U2.CK25(IO,_LVDS2C_44N,_DQ15) ; also on sheet 18
DDR4_DIMM_CH3_DQ5: U2.CM25(IO,_LVDS2C_44P,_DQ15) ; also on sheet 18
DDR4_DIMM_CH3_DQ6: U2.CN24(IO,_LVDS2C_43P,_DQ15) ; also on sheet 18
DDR4_DIMM_CH3_DQ7: U2.CL24(IO,_LVDS2C_43N,_DQ15) ; also on sheet 18
DDR4_DIMM_CH3_DQ8: U2.CG28(IO,_LVDS2C_41P,_DQ14) ; also on sheet 18
DDR4_DIMM_CH3_DQ9: U2.CH29(IO,_LVDS2C_42P,_DQ14) ; also on sheet 18
DDR4_DIMM_CH3_DQ10: U2.CE28(IO,_LVDS2C_41N,_DQ14) ; also on sheet 18
DDR4_DIMM_CH3_DQ11: U2.CF29(IO,_LVDS2C_42N,_DQ14) ; also on sheet 18
DDR4_DIMM_CH3_DQ12: U2.CE24(IO,_CLK_B_2C_0N,_LVDS2C_37N,_DQ14) ; also on sheet 18
DDR4_DIMM_CH3_DQ13: U2.CH25(IO,_LVDS2C_38P,_DQ14) ; also on sheet 18
DDR4_DIMM_CH3_DQ14: U2.CF25(IO,_LVDS2C_38N,_DQ14) ; also on sheet 18
DDR4_DIMM_CH3_DQ15: U2.CG24(IO,_CLK_B_2C_0P,_LVDS2C_37P,_DQ14) ; also on sheet 18
DDR4_DIMM_CH3_DQ16: U2.CH21(IO,_LVDS2C_29P,_DQ12) ; also on sheet 18
DDR4_DIMM_CH3_DQ17: U2.CF21(IO,_LVDS2C_29N,_DQ12) ; also on sheet 18
DDR4_DIMM_CH3_DQ18: U2.CE22(IO,_LVDS2C_30N,_DQ12) ; also on sheet 18
DDR4_DIMM_CH3_DQ19: U2.CG22(IO,_LVDS2C_30P,_DQ12) ; also on sheet 18
DDR4_DIMM_CH3_DQ20: U2.CE18(IO,_LVDS2C_26N,_DQ12) ; also on sheet 18
DDR4_DIMM_CH3_DQ21: U2.CG18(IO,_LVDS2C_26P,_DQ12) ; also on sheet 18
DDR4_DIMM_CH3_DQ22: U2.CH17(IO,_LVDS2C_25P,_DQ12) ; also on sheet 18
DDR4_DIMM_CH3_DQ23: U2.CF17(IO,_LVDS2C_25N,_DQ12) ; also on sheet 18
DDR4_DIMM_CH3_DQ24: U2.DC28(IO,_LVDS2C_23P,_DQ11) ; also on sheet 18
DDR4_DIMM_CH3_DQ25: U2.DA28(IO,_LVDS2C_23N,_DQ11) ; also on sheet 18
DDR4_DIMM_CH3_DQ26: U2.CY29(IO,_LVDS2C_24N,_DQ11) ; also on sheet 18
DDR4_DIMM_CH3_DQ27: U2.DB29(IO,_LVDS2C_24P,_DQ11) ; also on sheet 18
DDR4_DIMM_CH3_DQ28: U2.CY25(IO,_LVDS2C_20N,_DQ11) ; also on sheet 18
DDR4_DIMM_CH3_DQ29: U2.DB25(IO,_LVDS2C_20P,_DQ11) ; also on sheet 18
DDR4_DIMM_CH3_DQ30: U2.DC24(IO,_LVDS2C_19P,_DQ11) ; also on sheet 18
DDR4_DIMM_CH3_DQ31: U2.DA24(IO,_LVDS2C_19N,_DQ11) ; also on sheet 18
DDR4_DIMM_CH3_DQ32: U2.CN14(IO,_LVDS2D_47P,_DQ7) ; also on sheet 18
DDR4_DIMM_CH3_DQ33: U2.CL14(IO,_LVDS2D_47N,_DQ7) ; also on sheet 18
DDR4_DIMM_CH3_DQ34: U2.CK15(IO,_LVDS2D_48N,_DQ7) ; also on sheet 18
DDR4_DIMM_CH3_DQ35: U2.CM15(IO,_LVDS2D_48P,_DQ7) ; also on sheet 18
DDR4_DIMM_CH3_DQ36: U2.CK11(IO,_LVDS2D_44N,_DQ7) ; also on sheet 18
DDR4_DIMM_CH3_DQ37: U2.CM11(IO,_LVDS2D_44P,_DQ7) ; also on sheet 18
DDR4_DIMM_CH3_DQ38: U2.CN10(IO,_LVDS2D_43P,_DQ7) ; also on sheet 18
DDR4_DIMM_CH3_DQ39: U2.CL10(IO,_LVDS2D_43N,_DQ7) ; also on sheet 18
DDR4_DIMM_CH3_DQ40: U2.CG14(IO,_LVDS2D_41P,_DQ6) ; also on sheet 18
DDR4_DIMM_CH3_DQ41: U2.CH15(IO,_LVDS2D_42P,_DQ6) ; also on sheet 18
DDR4_DIMM_CH3_DQ42: U2.CE14(IO,_LVDS2D_41N,_DQ6) ; also on sheet 18
DDR4_DIMM_CH3_DQ43: U2.CF15(IO,_LVDS2D_42N,_DQ6) ; also on sheet 18
DDR4_DIMM_CH3_DQ44: U2.CE10(IO,_CLK_B_2D_0N,_LVDS2D_37N,_DQ6) ; also on sheet 18
DDR4_DIMM_CH3_DQ45: U2.CH11(IO,_LVDS2D_38P,_DQ6) ; also on sheet 18
DDR4_DIMM_CH3_DQ46: U2.CF11(IO,_LVDS2D_38N,_DQ6) ; also on sheet 18
DDR4_DIMM_CH3_DQ47: U2.CG10(IO,_CLK_B_2D_0P,_LVDS2D_37P,_DQ6) ; also on sheet 18
DDR4_DIMM_CH3_DQ48: U2.CM7(IO,_RZQ_B_2D,_LVDS2D_35P,_DQ5) ; also on sheet 18
DDR4_DIMM_CH3_DQ49: U2.CN8(IO,_CLK_B_2D_1P,_LVDS2D_36P,_DQ5) ; also on sheet 18
DDR4_DIMM_CH3_DQ50: U2.CK7(IO,_LVDS2D_35N,_DQ5) ; also on sheet 18
DDR4_DIMM_CH3_DQ51: U2.CL8(IO,_CLK_B_2D_1N,_LVDS2D_36N,_DQ5) ; also on sheet 18
DDR4_DIMM_CH3_DQ52: U2.CK3(IO,_LVDS2D_31N,_DQ5) ; also on sheet 18
DDR4_DIMM_CH3_DQ53: U2.CN4(IO,_LVDS2D_32P,_DQ5) ; also on sheet 18
DDR4_DIMM_CH3_DQ54: U2.CL4(IO,_LVDS2D_32N,_DQ5) ; also on sheet 18
DDR4_DIMM_CH3_DQ55: U2.CM3(IO,_LVDS2D_31P,_DQ5) ; also on sheet 18
DDR4_DIMM_CH3_DQ56: U2.CH7(IO,_LVDS2D_29P,_DQ4) ; also on sheet 18
DDR4_DIMM_CH3_DQ57: U2.CF7(IO,_LVDS2D_29N,_DQ4) ; also on sheet 18
DDR4_DIMM_CH3_DQ58: U2.CE8(IO,_LVDS2D_30N,_DQ4) ; also on sheet 18
DDR4_DIMM_CH3_DQ59: U2.CG8(IO,_LVDS2D_30P,_DQ4) ; also on sheet 18
DDR4_DIMM_CH3_DQ60: U2.CE4(IO,_LVDS2D_26N,_DQ4) ; also on sheet 18
DDR4_DIMM_CH3_DQ61: U2.CG4(IO,_LVDS2D_26P,_DQ4) ; also on sheet 18
DDR4_DIMM_CH3_DQ62: U2.CH3(IO,_LVDS2D_25P,_DQ4) ; also on sheet 18
DDR4_DIMM_CH3_DQ63: U2.CF3(IO,_LVDS2D_25N,_DQ4) ; also on sheet 18
DDR4_DIMM_CH3_DQ64: U2.CM21(IO,_RZQ_B_2C,_LVDS2C_35P,_DQ13) ; also on sheet 18
DDR4_DIMM_CH3_DQ65: U2.CN22(IO,_CLK_B_2C_1P,_LVDS2C_36P,_DQ13) ; also on sheet 18
DDR4_DIMM_CH3_DQ66: U2.CK21(IO,_LVDS2C_35N,_DQ13) ; also on sheet 18
DDR4_DIMM_CH3_DQ67: U2.CL22(IO,_CLK_B_2C_1N,_LVDS2C_36N,_DQ13) ; also on sheet 18
DDR4_DIMM_CH3_DQ68: U2.CK17(IO,_LVDS2C_31N,_DQ13) ; also on sheet 18
DDR4_DIMM_CH3_DQ69: U2.CL18(IO,_LVDS2C_32N,_DQ13) ; also on sheet 18
DDR4_DIMM_CH3_DQ70: U2.CN18(IO,_LVDS2C_32P,_DQ13) ; also on sheet 18
DDR4_DIMM_CH3_DQ71: U2.CM17(IO,_LVDS2C_31P,_DQ13) ; also on sheet 18
DDR4_DIMM_CH3_DQS_N0: U2.CK27(IO,_LVDS2C_46N,_DQSN15) ; also on sheet 18
DDR4_DIMM_CH3_DQS_N1: U2.CF27(IO,_LVDS2C_40N,_DQSN14) ; also on sheet 18
DDR4_DIMM_CH3_DQS_N2: U2.CE20(IO,_LVDS2C_28N,_DQSN12) ; also on sheet 18
DDR4_DIMM_CH3_DQS_N3: U2.CY27(IO,_LVDS2C_22N,_DQSN11) ; also on sheet 18
DDR4_DIMM_CH3_DQS_N4: U2.CK13(IO,_LVDS2D_46N,_DQSN7) ; also on sheet 18
DDR4_DIMM_CH3_DQS_N5: U2.CF13(IO,_LVDS2D_40N,_DQSN6) ; also on sheet 18
DDR4_DIMM_CH3_DQS_N6: U2.CL6(IO,_PLL_2D_B_CLKOUT1N,_LVDS2D_34N,_DQSN5) ; also on sheet 18
DDR4_DIMM_CH3_DQS_N7: U2.CE6(IO,_LVDS2D_28N,_DQSN4) ; also on sheet 18
DDR4_DIMM_CH3_DQS_N8: U2.CL20(IO,_PLL_2C_B_CLKOUT1N,_LVDS2C_34N,_DQSN13) ; also on sheet 18
DDR4_DIMM_CH3_DQS_P0: U2.CM27(IO,_LVDS2C_46P,_DQS15) ; also on sheet 18
DDR4_DIMM_CH3_DQS_P1: U2.CH27(IO,_LVDS2C_40P,_DQS14) ; also on sheet 18
DDR4_DIMM_CH3_DQS_P2: U2.CG20(IO,_LVDS2C_28P,_DQS12) ; also on sheet 18
DDR4_DIMM_CH3_DQS_P3: U2.DB27(IO,_LVDS2C_22P,_DQS11) ; also on sheet 18
DDR4_DIMM_CH3_DQS_P4: U2.CM13(IO,_LVDS2D_46P,_DQS7) ; also on sheet 18
DDR4_DIMM_CH3_DQS_P5: U2.CH13(IO,_LVDS2D_40P,_DQS6) ; also on sheet 18
DDR4_DIMM_CH3_DQS_P6: U2.CN6(IO,_PLL_2D_B_CLKOUT1P,_PLL_2D_B_CLKOUT1,_PLL_2D_B_FB1,_LVDS2D_34P,_DQS5) ; also on sheet 18
DDR4_DIMM_CH3_DQS_P7: U2.CG6(IO,_LVDS2D_28P,_DQS4) ; also on sheet 18
DDR4_DIMM_CH3_DQS_P8: U2.CN20(IO,_PLL_2C_B_CLKOUT1P,_PLL_2C_B_CLKOUT1,_PLL_2C_B_FB1,_LVDS2C_34P,_DQS13) ; also on sheet 18
DDR4_DIMM_CH3_ODT0: U2.DB13(IO,_LVDS2D_22P,_DQS3) ; also on sheet 18
DDR4_DIMM_CH3_ODT1: U2.CY13(IO,_LVDS2D_22N,_DQSN3) ; also on sheet 18
DDR4_DIMM_CH3_PAR: U2.DA10(IO,_LVDS2D_19N,_DQ3) ; also on sheet 18
DDR4_DIMM_CH3_RESET_N: U2.CY15(IO,_LVDS2D_24N,_DQ3) ; also on sheet 18
DDR4_DIMM_CH3_RZQ: R84.1 U2.DB7(IO,_RZQ_T_2D,_LVDS2D_11P,_DQ1)
DDR4_DIMM_CH3_TDQS_N9: U2.CL26(IO,_LVDS2C_45N,_DQ15) ; also on sheet 18
DDR4_DIMM_CH3_TDQS_N10: U2.CE26(IO,_PLL_2C_B_CLKOUT0N,_LVDS2C_39N,_DQ14) ; also on sheet 18
DDR4_DIMM_CH3_TDQS_N11: U2.CF19(IO,_LVDS2C_27N,_DQ12) ; also on sheet 18
DDR4_DIMM_CH3_TDQS_N12: U2.DA26(IO,_LVDS2C_21N,_DQ11) ; also on sheet 18
DDR4_DIMM_CH3_TDQS_N13: U2.CL12(IO,_LVDS2D_45N,_DQ7) ; also on sheet 18
DDR4_DIMM_CH3_TDQS_N14: U2.CE12(IO,_PLL_2D_B_CLKOUT0N,_LVDS2D_39N,_DQ6) ; also on sheet 18
DDR4_DIMM_CH3_TDQS_N15: U2.CK5(IO,_LVDS2D_33N,_DQ5) ; also on sheet 18
DDR4_DIMM_CH3_TDQS_N16: U2.CF5(IO,_LVDS2D_27N,_DQ4) ; also on sheet 18
DDR4_DIMM_CH3_TDQS_N17: U2.CK19(IO,_LVDS2C_33N,_DQ13) ; also on sheet 18
FPGA_PCIE_PERSTn: R89.2 U2.BU58(I_PIN_PERST_N_U10_P) ; also on sheet 44
FPGA_TEMP2n: U2.AG46(TEMPDIODE1N) ; also on sheet 47
FPGA_TEMP2p: U2.AH45(TEMPDIODE1P) ; also on sheet 47
FPGA_TEMP3n: U2.AR20(TEMPDIODE4N) ; also on sheet 47
FPGA_TEMP3p: U2.AN18(TEMPDIODE4P) ; also on sheet 47
IO_3p3V: C142.1 C143.2 C157.1 C158.2 L15.1 L16.1 L17.1 L18.1 L19.1 L20.1 R90.1 R91.1 R92.2 R93.2 R95.1 R96.1 ; also on sheet 12 25 28 30 31 38 39 40 41 42 63
PCIE_1V2_CLKREQn: U2.CR20(IO,_LVDS2C_4N,_DQSN8) ; also on sheet 25
PCIE_EP_I2C_SCL: R81.1 U2.CT19(IO,_LVDS2C_3N,_DQ8) ; also on sheet 25
PCIE_EP_I2C_SDA: R82.1 U2.CV17(IO,_LVDS2C_1P,_DQ8) ; also on sheet 25
PCIE_EP_RX_N0: U2.BR56(GXPL10A_TX_CH0N) ; also on sheet 25
PCIE_EP_RX_N1: U2.BM53(GXPL10A_TX_CH1N) ; also on sheet 25
PCIE_EP_RX_N2: U2.BL56(GXPL10A_TX_CH2N) ; also on sheet 25
PCIE_EP_RX_N3: U2.BH53(GXPL10A_TX_CH3N) ; also on sheet 25
PCIE_EP_RX_N4: U2.BG56(GXPL10A_TX_CH4N) ; also on sheet 25
PCIE_EP_RX_N5: U2.BD53(GXPL10A_TX_CH5N) ; also on sheet 25
PCIE_EP_RX_N6: U2.BC56(GXPL10A_TX_CH6N) ; also on sheet 25
PCIE_EP_RX_N7: U2.AY53(GXPL10A_TX_CH7N) ; also on sheet 25
PCIE_EP_RX_N8: U2.AW56(GXPL10A_TX_CH8N) ; also on sheet 25
PCIE_EP_RX_N9: U2.AT53(GXPL10A_TX_CH9N) ; also on sheet 25
PCIE_EP_RX_N10: U2.AR56(GXPL10A_TX_CH10N) ; also on sheet 25
PCIE_EP_RX_N11: U2.AM53(GXPL10A_TX_CH11N) ; also on sheet 25
PCIE_EP_RX_N12: U2.AL56(GXPL10A_TX_CH12N) ; also on sheet 25
PCIE_EP_RX_N13: U2.AH53(GXPL10A_TX_CH13N) ; also on sheet 25
PCIE_EP_RX_N14: U2.AG56(GXPL10A_TX_CH14N) ; also on sheet 25
PCIE_EP_RX_N15: U2.AD53(GXPL10A_TX_CH15N) ; also on sheet 25
PCIE_EP_RX_P0: U2.BP55(GXPL10A_TX_CH0P) ; also on sheet 25
PCIE_EP_RX_P1: U2.BN52(GXPL10A_TX_CH1P) ; also on sheet 25
PCIE_EP_RX_P2: U2.BK55(GXPL10A_TX_CH2P) ; also on sheet 25
PCIE_EP_RX_P3: U2.BJ52(GXPL10A_TX_CH3P) ; also on sheet 25
PCIE_EP_RX_P4: U2.BF55(GXPL10A_TX_CH4P) ; also on sheet 25
PCIE_EP_RX_P5: U2.BE52(GXPL10A_TX_CH5P) ; also on sheet 25
PCIE_EP_RX_P6: U2.BB55(GXPL10A_TX_CH6P) ; also on sheet 25
PCIE_EP_RX_P7: U2.BA52(GXPL10A_TX_CH7P) ; also on sheet 25
PCIE_EP_RX_P8: U2.AV55(GXPL10A_TX_CH8P) ; also on sheet 25
PCIE_EP_RX_P9: U2.AU52(GXPL10A_TX_CH9P) ; also on sheet 25
PCIE_EP_RX_P10: U2.AP55(GXPL10A_TX_CH10P) ; also on sheet 25
PCIE_EP_RX_P11: U2.AN52(GXPL10A_TX_CH11P) ; also on sheet 25
PCIE_EP_RX_P12: U2.AK55(GXPL10A_TX_CH12P) ; also on sheet 25
PCIE_EP_RX_P13: U2.AJ52(GXPL10A_TX_CH13P) ; also on sheet 25
PCIE_EP_RX_P14: U2.AF55(GXPL10A_TX_CH14P) ; also on sheet 25
PCIE_EP_RX_P15: U2.AE52(GXPL10A_TX_CH15P) ; also on sheet 25
PCIE_EP_TX_N0: U2.BR62(GXPL10A_RX_CH0N) ; also on sheet 25
PCIE_EP_TX_N1: U2.BM59(GXPL10A_RX_CH1N) ; also on sheet 25
PCIE_EP_TX_N2: U2.BL62(GXPL10A_RX_CH2N) ; also on sheet 25
PCIE_EP_TX_N3: U2.BH59(GXPL10A_RX_CH3N) ; also on sheet 25
PCIE_EP_TX_N4: U2.BG62(GXPL10A_RX_CH4N) ; also on sheet 25
PCIE_EP_TX_N5: U2.BD59(GXPL10A_RX_CH5N) ; also on sheet 25
PCIE_EP_TX_N6: U2.BC62(GXPL10A_RX_CH6N) ; also on sheet 25
PCIE_EP_TX_N7: U2.AY59(GXPL10A_RX_CH7N) ; also on sheet 25
PCIE_EP_TX_N8: U2.AW62(GXPL10A_RX_CH8N) ; also on sheet 25
PCIE_EP_TX_N9: U2.AT59(GXPL10A_RX_CH9N) ; also on sheet 25
PCIE_EP_TX_N10: U2.AR62(GXPL10A_RX_CH10N) ; also on sheet 25
PCIE_EP_TX_N11: U2.AM59(GXPL10A_RX_CH11N) ; also on sheet 25
PCIE_EP_TX_N12: U2.AL62(GXPL10A_RX_CH12N) ; also on sheet 25
PCIE_EP_TX_N13: U2.AH59(GXPL10A_RX_CH13N) ; also on sheet 25
PCIE_EP_TX_N14: U2.AG62(GXPL10A_RX_CH14N) ; also on sheet 25
PCIE_EP_TX_N15: U2.AD59(GXPL10A_RX_CH15N) ; also on sheet 25
PCIE_EP_TX_P0: U2.BP61(GXPL10A_RX_CH0P) ; also on sheet 25
PCIE_EP_TX_P1: U2.BN58(GXPL10A_RX_CH1P) ; also on sheet 25
PCIE_EP_TX_P2: U2.BK61(GXPL10A_RX_CH2P) ; also on sheet 25
PCIE_EP_TX_P3: U2.BJ58(GXPL10A_RX_CH3P) ; also on sheet 25
PCIE_EP_TX_P4: U2.BF61(GXPL10A_RX_CH4P) ; also on sheet 25
PCIE_EP_TX_P5: U2.BE58(GXPL10A_RX_CH5P) ; also on sheet 25
PCIE_EP_TX_P6: U2.BB61(GXPL10A_RX_CH6P) ; also on sheet 25
PCIE_EP_TX_P7: U2.BA58(GXPL10A_RX_CH7P) ; also on sheet 25
PCIE_EP_TX_P8: U2.AV61(GXPL10A_RX_CH8P) ; also on sheet 25
PCIE_EP_TX_P9: U2.AU58(GXPL10A_RX_CH9P) ; also on sheet 25
PCIE_EP_TX_P10: U2.AP61(GXPL10A_RX_CH10P) ; also on sheet 25
PCIE_EP_TX_P11: U2.AN58(GXPL10A_RX_CH11P) ; also on sheet 25
PCIE_EP_TX_P12: U2.AK61(GXPL10A_RX_CH12P) ; also on sheet 25
PCIE_EP_TX_P13: U2.AJ58(GXPL10A_RX_CH13P) ; also on sheet 25
PCIE_EP_TX_P14: U2.AF61(GXPL10A_RX_CH14P) ; also on sheet 25
PCIE_EP_TX_P15: U2.AE58(GXPL10A_RX_CH15P) ; also on sheet 25
PCIE_EP_WAKEN: R83.1 U2.CR18(IO,_LVDS2C_2N,_DQ8) ; also on sheet 25
QSFPDD0_3V3_INT_L: J5.28(INTL) R90.2 ; also on sheet 44
QSFPDD0_3V3_LPMODE: J5.31(INITMODE) ; also on sheet 44
QSFPDD0_3V3_MODPRS_L: J5.27(MODPRSL) R91.2 ; also on sheet 44
QSFPDD0_3V3_MODSEL_L: J5.8(MODSELL) ; also on sheet 44
QSFPDD0_3V3_RESET_L: J5.9(RESETL) ; also on sheet 44
QSFPDD0_RX0_N: J5.18(RX1N) U2.AJ8(GXER9A_RX_CH0N)
QSFPDD0_RX0_P: J5.17(RX1P) U2.AK7(GXER9A_RX_CH0P)
QSFPDD0_RX1_N: J5.21(RX2N) U2.AN8(GXER9A_RX_CH2N)
QSFPDD0_RX1_P: J5.22(RX2P) U2.AP7(GXER9A_RX_CH2P)
QSFPDD0_RX2_N: J5.15(RX3N) U2.AM11(GXER9A_RX_CH1N)
QSFPDD0_RX2_P: J5.14(RX3P) U2.AL10(GXER9A_RX_CH1P)
QSFPDD0_RX3_N: J5.24(RX4N) U2.AT11(GXER9A_RX_CH3N)
QSFPDD0_RX3_P: J5.25(RX4P) U2.AR10(GXER9A_RX_CH3P)
QSFPDD0_RX4_N: J5.56(RX5N) U2.AU8(GXER9A_RX_CH8N)
QSFPDD0_RX4_P: J5.55(RX5P) U2.AV7(GXER9A_RX_CH8P)
QSFPDD0_RX5_N: J5.59(RX6N) U2.BA8(GXER9A_RX_CH10N)
QSFPDD0_RX5_P: J5.60(RX6P) U2.BB7(GXER9A_RX_CH10P)
QSFPDD0_RX6_N: J5.53(RX7N) U2.AY11(GXER9A_RX_CH9N)
QSFPDD0_RX6_P: J5.52(RX7P) U2.AW10(GXER9A_RX_CH9P)
QSFPDD0_RX7_N: J5.62(RX8N) U2.BD11(GXER9A_RX_CH11N)
QSFPDD0_RX7_P: J5.63(RX8P) U2.BC10(GXER9A_RX_CH11P)
QSFPDD0_TX0_N: J5.37(TX1N) U2.AJ2(GXER9A_TX_CH0N)
QSFPDD0_TX0_P: J5.36(TX1P) U2.AK1(GXER9A_TX_CH0P)
QSFPDD0_TX1_N: J5.2(TX2N) U2.AN2(GXER9A_TX_CH2N)
QSFPDD0_TX1_P: J5.3(TX2P) U2.AP1(GXER9A_TX_CH2P)
QSFPDD0_TX2_N: J5.34(TX3N) U2.AM5(GXER9A_TX_CH1N)
QSFPDD0_TX2_P: J5.33(TX3P) U2.AL4(GXER9A_TX_CH1P)
QSFPDD0_TX3_N: J5.5(TX4N) U2.AT5(GXER9A_TX_CH3N)
QSFPDD0_TX3_P: J5.6(TX4P) U2.AR4(GXER9A_TX_CH3P)
QSFPDD0_TX4_N: J5.75(TX5N) U2.AU2(GXER9A_TX_CH8N)
QSFPDD0_TX4_P: J5.74(TX5P) U2.AV1(GXER9A_TX_CH8P)
QSFPDD0_TX5_N: J5.40(TX6N) U2.BA2(GXER9A_TX_CH10N)
QSFPDD0_TX5_P: J5.41(TX6P) U2.BB1(GXER9A_TX_CH10P)
QSFPDD0_TX6_N: J5.72(TX7N) U2.AY5(GXER9A_TX_CH9N)
QSFPDD0_TX6_P: J5.71(TX7P) U2.AW4(GXER9A_TX_CH9P)
QSFPDD0_TX7_N: J5.43(TX8N) U2.BD5(GXER9A_TX_CH11N)
QSFPDD0_TX7_P: J5.44(TX8P) U2.BC4(GXER9A_TX_CH11P)
QSFPDD0_VCC: C152.1 C153.2 C154.2 C155.2 J5.30(VCC1) J5.68(VCC2) L17.2
QSFPDD0_VCCR: C148.1 C149.2 C150.2 C151.2 J5.10(VCCRX) J5.48(VCCRX1) L16.2
QSFPDD0_VCCT: C144.1 C145.2 C146.2 C147.2 J5.29(VCCTX) J5.67(VCCTX1) L15.2
QSFPDD1_3V3_INT_L: J6.28(INTL) R95.2 ; also on sheet 44
QSFPDD1_3V3_LPMODE: J6.31(INITMODE) ; also on sheet 44
QSFPDD1_3V3_MODPRS_L: J6.27(MODPRSL) R96.2 ; also on sheet 44
QSFPDD1_3V3_MODSEL_L: J6.8(MODSELL) ; also on sheet 44
QSFPDD1_3V3_RESET_L: J6.9(RESETL) ; also on sheet 44
QSFPDD1_RX0_N: J6.18(RX1N) U2.BE8(GXER9A_RX_CH12N)
QSFPDD1_RX0_P: J6.17(RX1P) U2.BF7(GXER9A_RX_CH12P)
QSFPDD1_RX1_N: J6.21(RX2N) U2.BJ8(GXER9A_RX_CH14N)
QSFPDD1_RX1_P: J6.22(RX2P) U2.BK7(GXER9A_RX_CH14P)
QSFPDD1_RX2_N: J6.15(RX3N) U2.BH11(GXER9A_RX_CH13N)
QSFPDD1_RX2_P: J6.14(RX3P) U2.BG10(GXER9A_RX_CH13P)
QSFPDD1_RX3_N: J6.24(RX4N) U2.BM11(GXER9A_RX_CH15N)
QSFPDD1_RX3_P: J6.25(RX4P) U2.BL10(GXER9A_RX_CH15P)
QSFPDD1_RX4_N: J6.56(RX5N) U2.BN8(GXER9A_RX_CH20N)
QSFPDD1_RX4_P: J6.55(RX5P) U2.BP7(GXER9A_RX_CH20P)
QSFPDD1_RX5_N: J6.59(RX6N) U2.BU8(GXER9A_RX_CH22N)
QSFPDD1_RX5_P: J6.60(RX6P) U2.BV7(GXER9A_RX_CH22P)
QSFPDD1_RX6_N: J6.53(RX7N) U2.BT11(GXER9A_RX_CH21N)
QSFPDD1_RX6_P: J6.52(RX7P) U2.BR10(GXER9A_RX_CH21P)
QSFPDD1_RX7_N: J6.62(RX8N) U2.BY11(GXER9A_RX_CH23N)
QSFPDD1_RX7_P: J6.63(RX8P) U2.BW10(GXER9A_RX_CH23P)
QSFPDD1_TX0_N: J6.37(TX1N) U2.BE2(GXER9A_TX_CH12N)
QSFPDD1_TX0_P: J6.36(TX1P) U2.BF1(GXER9A_TX_CH12P)
QSFPDD1_TX1_N: J6.2(TX2N) U2.BJ2(GXER9A_TX_CH14N)
QSFPDD1_TX1_P: J6.3(TX2P) U2.BK1(GXER9A_TX_CH14P)
QSFPDD1_TX2_N: J6.34(TX3N) U2.BH5(GXER9A_TX_CH13N)
QSFPDD1_TX2_P: J6.33(TX3P) U2.BG4(GXER9A_TX_CH13P)
QSFPDD1_TX3_N: J6.5(TX4N) U2.BM5(GXER9A_TX_CH15N)
QSFPDD1_TX3_P: J6.6(TX4P) U2.BL4(GXER9A_TX_CH15P)
QSFPDD1_TX4_N: J6.75(TX5N) U2.BN2(GXER9A_TX_CH20N)
QSFPDD1_TX4_P: J6.74(TX5P) U2.BP1(GXER9A_TX_CH20P)
QSFPDD1_TX5_N: J6.40(TX6N) U2.BU2(GXER9A_TX_CH22N)
QSFPDD1_TX5_P: J6.41(TX6P) U2.BV1(GXER9A_TX_CH22P)
QSFPDD1_TX6_N: J6.72(TX7N) U2.BT5(GXER9A_TX_CH21N)
QSFPDD1_TX6_P: J6.71(TX7P) U2.BR4(GXER9A_TX_CH21P)
QSFPDD1_TX7_N: J6.43(TX8N) U2.BY5(GXER9A_TX_CH23N)
QSFPDD1_TX7_P: J6.44(TX8P) U2.BW4(GXER9A_TX_CH23P)
QSFPDD1_VCC: C167.1 C168.2 C169.2 C170.2 J6.30(VCC1) J6.68(VCC2) L20.2
QSFPDD1_VCCR: C163.1 C164.2 C165.2 C166.2 J6.10(VCCRX) J6.48(VCCRX1) L19.2
QSFPDD1_VCCT: C159.1 C160.2 C161.2 C162.2 J6.29(VCCTX) J6.67(VCCTX1) L18.2
QSFPDD_I2C_SCL: J5.11(SCL) J6.11(SCL) R92.1 ; also on sheet 12
QSFPDD_I2C_SDA: J5.12(SDA) J6.12(SDA) R93.1 ; also on sheet 12
REFCLK_156M_QSFPDD_N: R811.1 U2.AN14(REFCLK_GXER9A_CH1N) ; also on sheet 38
REFCLK_156M_QSFPDD_P: R811.2 U2.AR14(REFCLK_GXER9A_CH1P) ; also on sheet 38
REFCLK_322M_QSFPDD_N: R810.1 U2.AP13(REFCLK_GXER9A_CH0N) ; also on sheet 38
REFCLK_322M_QSFPDD_P: R810.2 U2.AT13(REFCLK_GXER9A_CH0P) ; also on sheet 38
REFCLK_PCIE_CH0_N: R812.1 U2.AH49(REFCLK_GXPL10A_CH0N) ; also on sheet 39
REFCLK_PCIE_CH0_P: R812.2 U2.AJ48(REFCLK_GXPL10A_CH0P) ; also on sheet 39
REFCLK_PCIE_CH2_N: R813.2 U2.AD49(REFCLK_GXPL10A_CH2N) ; also on sheet 39
REFCLK_PCIE_CH2_P: R813.1 U2.AE48(REFCLK_GXPL10A_CH2P) ; also on sheet 39
N36227679: R86.1 U2.AN20(IO_AUX_RREF20)
N36227711: R88.2 U2.BM43(IO_AUX_RREF10_P)
N36227759: R87.2 U2.BH49(U10_P_IO_RESREF_0)
N38301581: R5757.1 U2.AT19(DNU17)
N38301586: R5758.1 U2.AP17(DNU18)

Not connected (* = marked no-connect by the designer): J5 46(RESERVED1)* 47(VS1)* 49(VS2)* 50(VS3)* 65(NC)* 66(RESERVED2)* 69(RESERVED3)* 77(MTH1)* 78(MTH2)*; J6 46(RESERVED1)* 47(VS1)* 49(VS2)* 50(VS3)* 65(NC)* 66(RESERVED2)* 69(RESERVED3)* 77(MTH1)* 78(MTH2)*; U2 AM19(DNU16)* AT17(DNU19)* CR4(IO,_LVDS2D_2N,_DQ0)* CR6(IO,_LVDS2D_4N,_DQSN0)* CR22(IO,_LVDS2C_6N,_DQ8)* CR26(IO,_PLL_2C_T_CLKOUT0N,_LVDS2C_15N,_DQ10)* CR28(IO,_LVDS2C_17N,_DQ10)* CT5(IO,_LVDS2D_3N,_DQ0)* CT7(IO,_LVDS2D_5N,_DQ0)* CT17(IO,_LVDS2C_1N,_DQ8)* CT21(IO,_LVDS2C_5N,_DQ8)* CT25(IO,_LVDS2C_14N,_DQ10)* CT27(IO,_LVDS2C_16N,_DQSN10)* CT29(IO,_LVDS2C_18N,_DQ10)* CU6(IO,_LVDS2D_4P,_DQS0)* CU18(IO,_LVDS2C_2P,_DQ8)* CU20(IO,_LVDS2C_4P,_DQS8)* CU22(IO,_LVDS2C_6P,_DQ8)* CU26(IO,_PLL_2C_T_CLKOUT0P,_PLL_2C_T_CLKOUT0,_PLL_2C_T_FB0,_LVDS2C_15P,_DQ10)* CU28(IO,_LVDS2C_17P,_DQ10)* CV5(IO,_LVDS2D_3P,_DQ0)* CV19(IO,_LVDS2C_3P,_DQ8)* CV21(IO,_LVDS2C_5P,_DQ8)* CV25(IO,_LVDS2C_14P,_DQ10)* CV27(IO,_LVDS2C_16P,_DQS10)* CV29(IO,_LVDS2C_18P,_DQ10)* CY17(IO,_LVDS2C_7N,_DQ9)* CY19(IO,_LVDS2C_9N,_DQ9)* CY21(IO,_LVDS2C_11N,_DQ9)* DA18(IO,_LVDS2C_8N,_DQ9)* DA20(IO,_PLL_2C_T_CLKOUT1N,_LVDS2C_10N,_DQSN9)* DA22(IO,_CLK_T_2C_1N,_LVDS2C_12N,_DQ9)* DB17(IO,_LVDS2C_7P,_DQ9)* DB19(IO,_LVDS2C_9P,_DQ9)* DB21(IO,_RZQ_T_2C,_LVDS2C_11P,_DQ9)* DC18(IO,_LVDS2C_8P,_DQ9)* DC20(IO,_PLL_2C_T_CLKOUT1P,_PLL_2C_T_CLKOUT1,_PLL_2C_T_FB1,_LVDS2C_10P,_DQS9)* DC22(IO,_CLK_T_2C_1P,_LVDS2C_12P,_DQ9)*

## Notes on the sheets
sheet 19
- DDR4/T CH3 INTERFACE -- FPGA SIDE 2C
sheet 20
- DDR4/T CH3 INTERFACE -- FPGA SIDE 2D
- DDRT:ERID2
- DDRT:ERID0
- DDRT:NC
- DDRT:C2
- DDRT:C3
- DDRT:C1
- DDRT:GNT0
- DDRT:REQ
- DDRT:ERR
sheet 21
- E-TILE BANK 9A
- NOTE: This pins are
  for internal use only
sheet 22
- P-TILE BANK 10A
sheet 23
- QSFPDD0
- NOTE 1: Bypass Capacitors should be placed as close to the associated 20-pin
  connector as possible.
- NOTE 2: zQSFP 100-ohm termination is implemented via the FPGA on-chip termination.
- NOTE 3: DC blocking capacitors are in the module for RX and TX.
- NOTE 4: 1uH inductors should have a DC Resistance of less than 0.1-ohm.
- Place close to QSFPDD Connector
- Guide Pins
- Guide Pins
- MOLEX MPN 2031431355
sheet 24
- QSFPDD1
- NOTE 1: Bypass Capacitors should be placed as close to the associated 20-pin
  connector as possible.
- NOTE 2: zQSFP 100-ohm termination is implemented via the FPGA on-chip termination.
- NOTE 3: DC blocking capacitors are in the module for RX and TX.
- NOTE 4: 1uH inductors should have a DC Resistance of less than 0.1-ohm.
- Place close to QSFPDD Connector
- Guide Pins
- Guide Pins
- MOLEX MPN 2031431355
